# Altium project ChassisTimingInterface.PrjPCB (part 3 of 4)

## Sheet FPGA_ARTIX7.SchDoc: FPGA
size C; Organization: Altium Limited; Address1: L3, 12a Rodborough Rd; Address2: Frenchs Forest; Address3: NSW; Address4: Australia 2086; DocumentNumber: 7; SheetNumber: 7; SheetTotal: 12
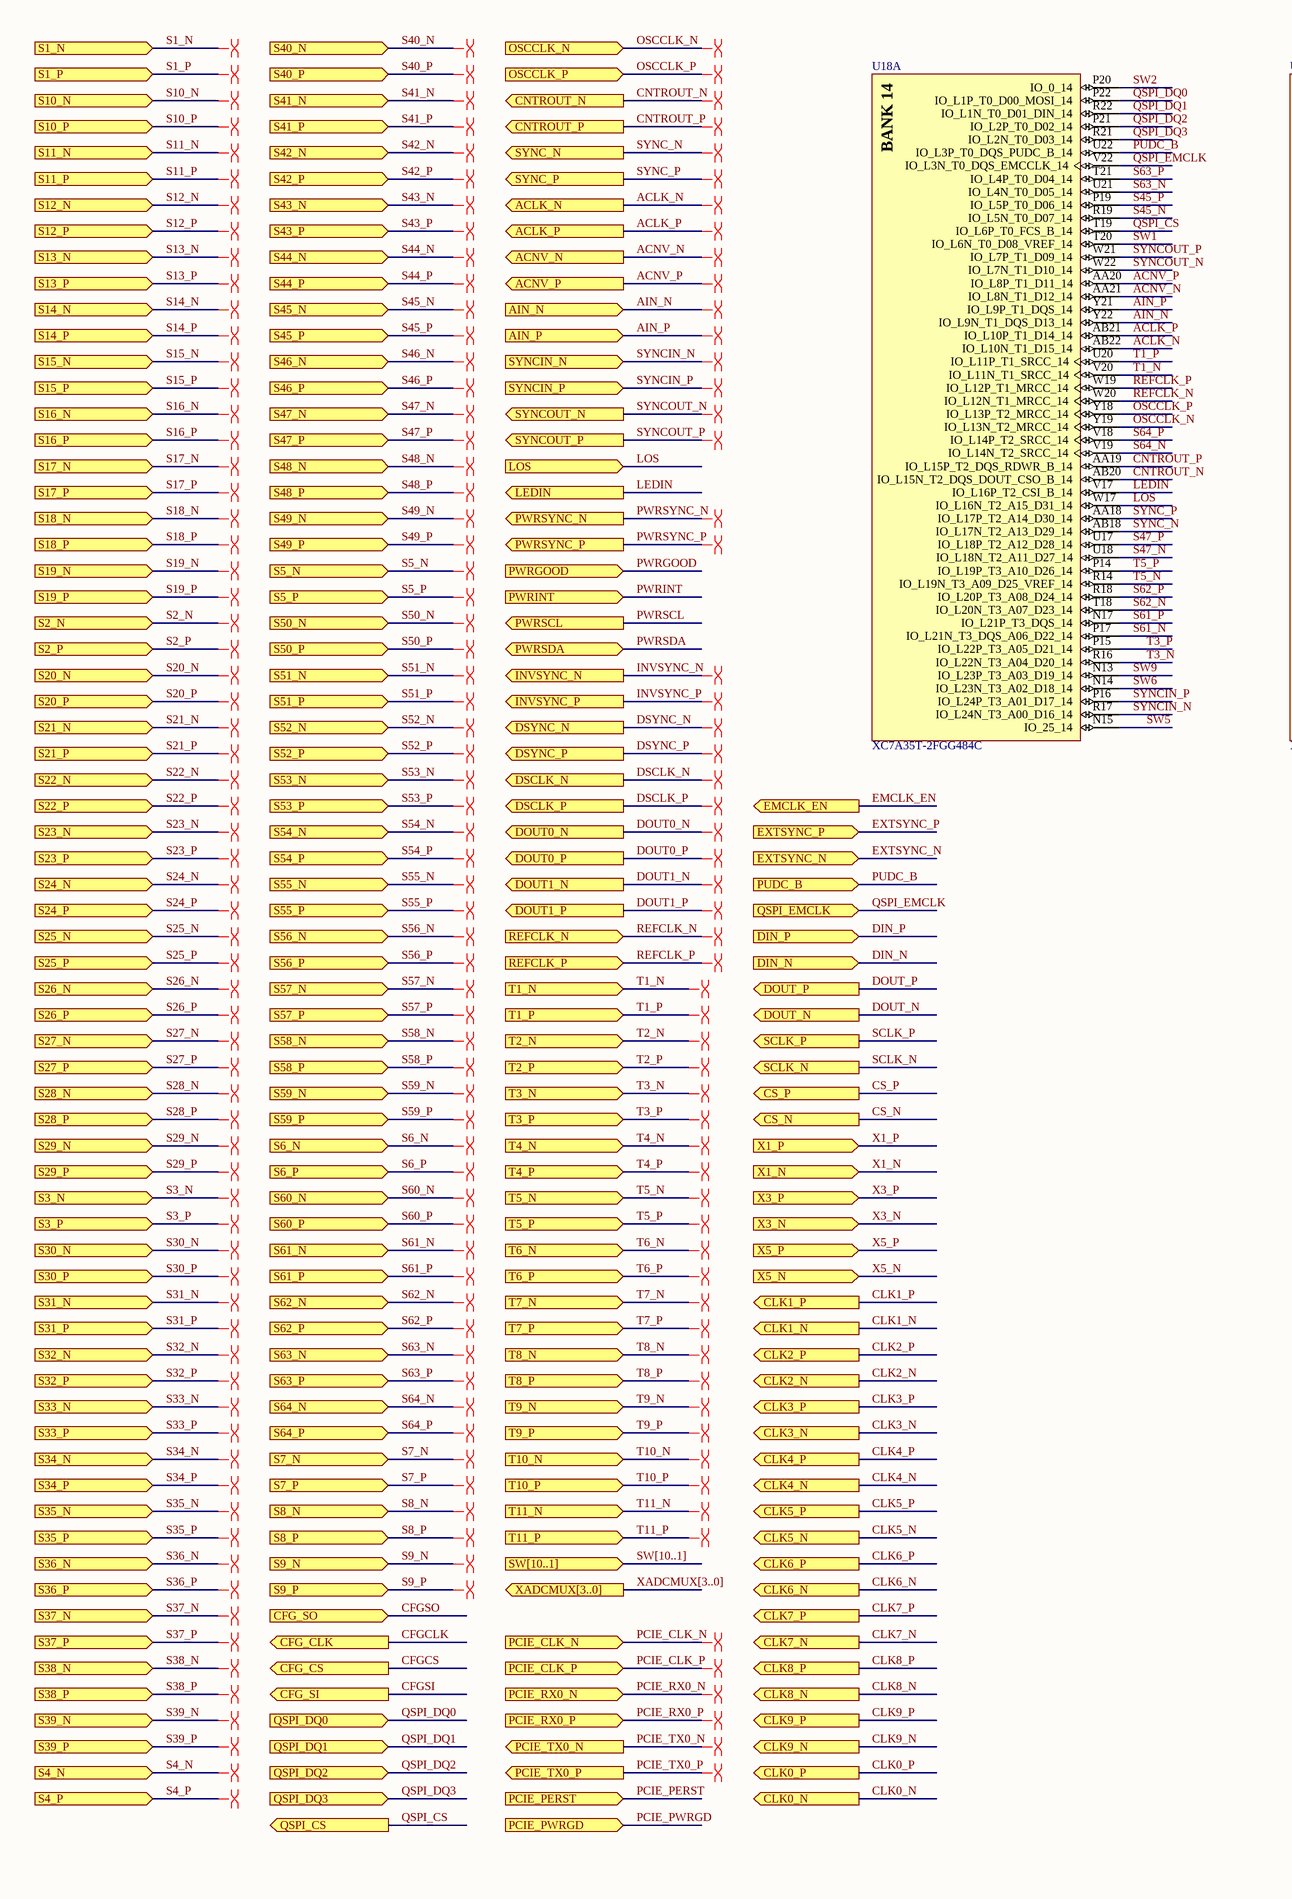
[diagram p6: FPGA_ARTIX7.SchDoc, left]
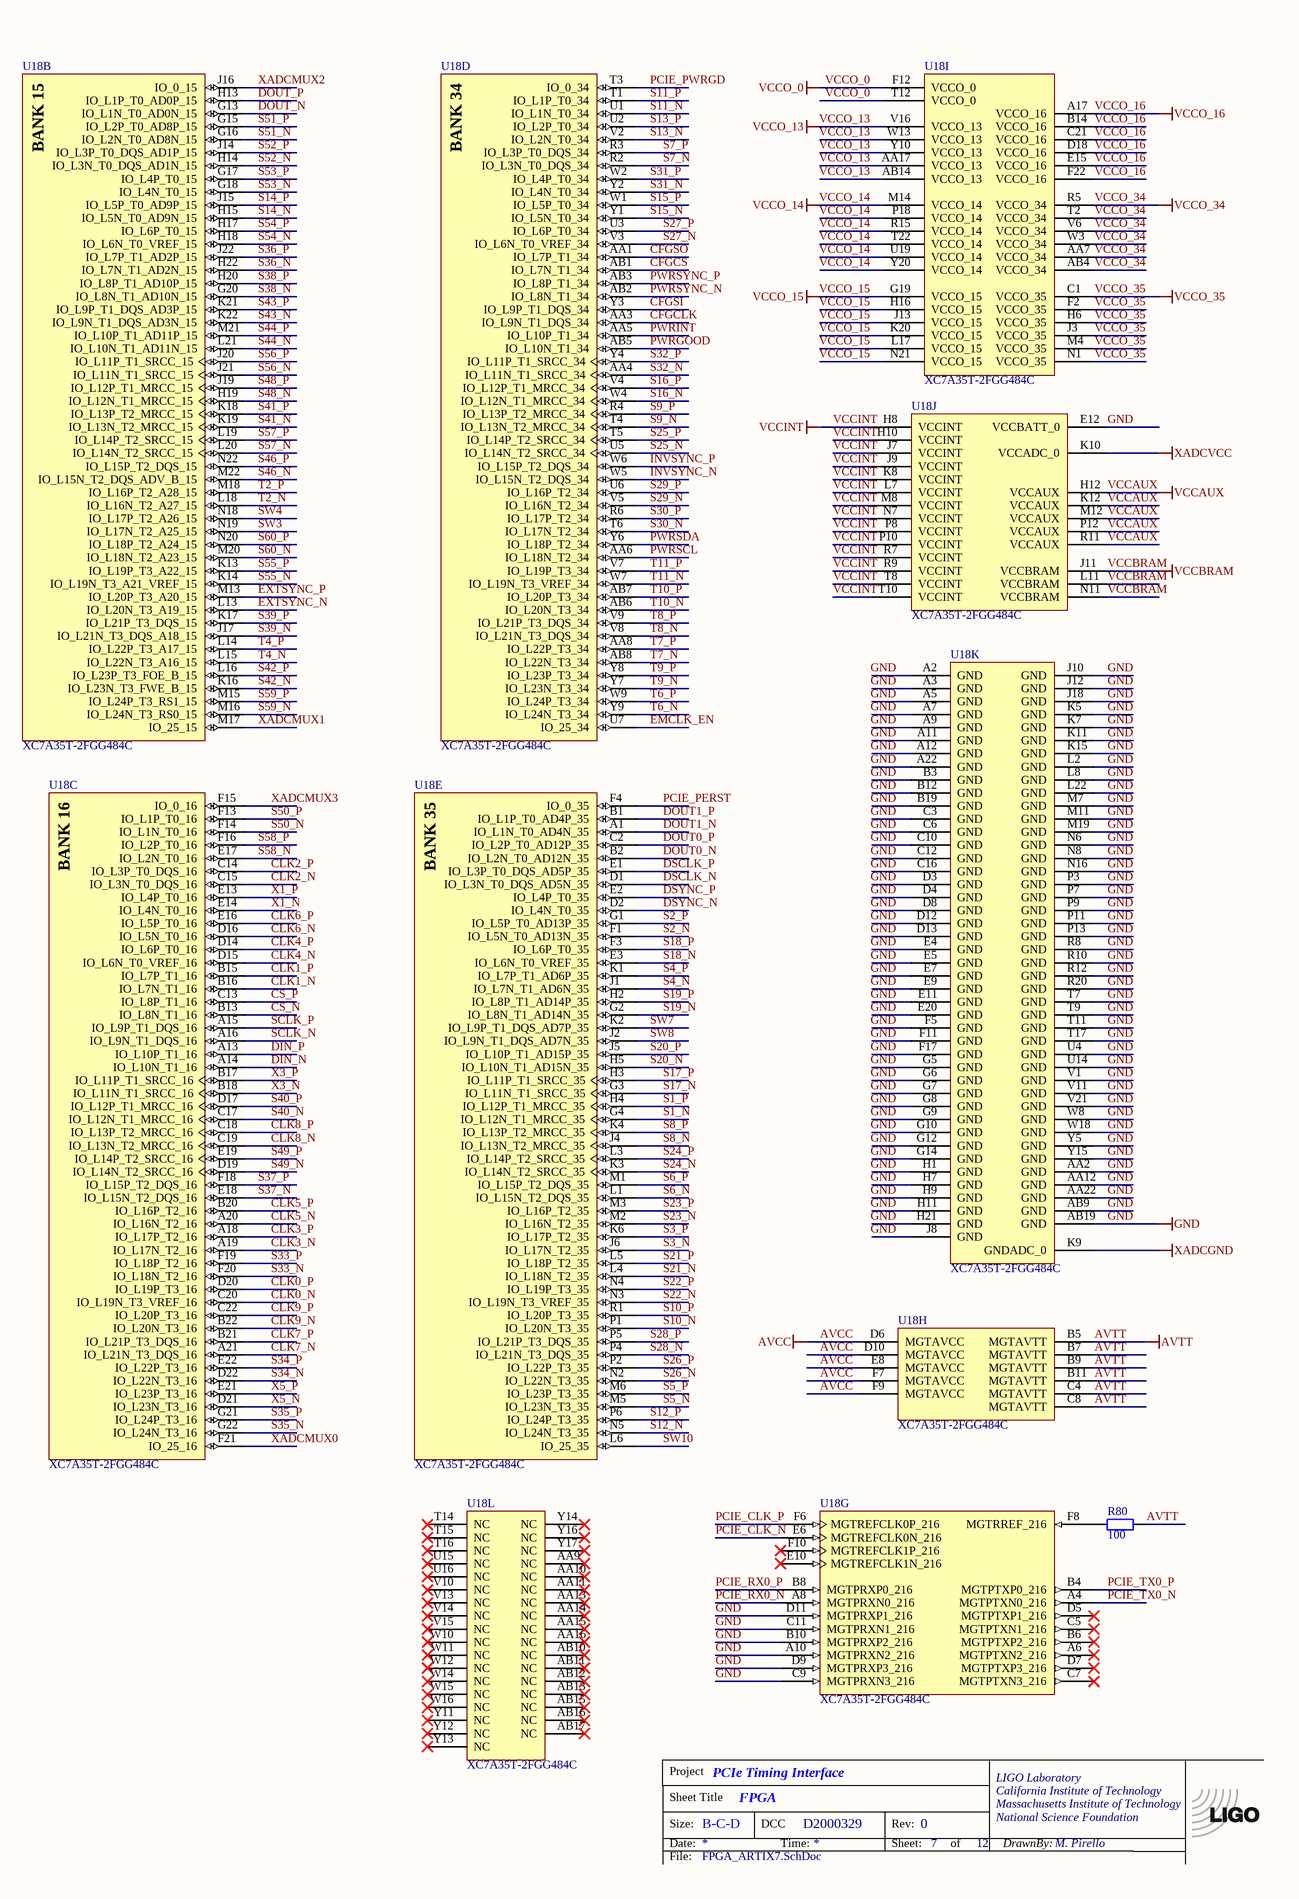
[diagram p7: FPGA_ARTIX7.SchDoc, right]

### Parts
(Parts that share a designator on the sheet are numbered #1, #2 ... from top to bottom, then left to right.)
*?#4  TitleBlock  (value not drawn)  (graphical)
R80  100  [CR1608-0603]
U18  XC7A35T-2FGG484C  [FGG484]  (parts A,B,C,D,E,G,H,I,J,K,L of 12)

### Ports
ACLK_N (out), ACLK_P (out), ACNV_N (out), ACNV_P (out), AIN_N (in), AIN_P (in), CFG_CLK (out), CFG_CS (out), CFG_SI (out), CFG_SO (in), CLK0_N (out), CLK0_P (out), CLK1_N (out), CLK1_P (out), CLK2_N (out), CLK2_P (out), CLK3_N (out), CLK3_P (out), CLK4_N (out), CLK4_P (out), CLK5_N (out), CLK5_P (out), CLK6_N (out), CLK6_P (out), CLK7_N (out), CLK7_P (out), CLK8_N (out), CLK8_P (out), CLK9_N (out), CLK9_P (out), CNTROUT_N (out), CNTROUT_P (out), CS_N (out), CS_P (out), DIN_N (in), DIN_P (in), DOUT0_N (out), DOUT0_P (out), DOUT1_N (out), DOUT1_P (out), DOUT_N (out), DOUT_P (out), DSCLK_N (out), DSCLK_P (out), DSYNC_N (out), DSYNC_P (out), EMCLK_EN (out), EXTSYNC_N (in), EXTSYNC_P (in), INVSYNC_N (out), INVSYNC_P (out), LEDIN (out), LOS (in), OSCCLK_N (in), OSCCLK_P (in), PCIE_CLK_N (in), PCIE_CLK_P (in), PCIE_PERST (in), PCIE_PWRGD (in), PCIE_RX0_N (in), PCIE_RX0_P (in), PCIE_TX0_N (out), PCIE_TX0_P (out), PUDC_B (in), PWRGOOD (in), PWRINT (in), PWRSCL (out), PWRSDA (bidir), PWRSYNC_N (out), PWRSYNC_P (out), QSPI_CS (out), QSPI_DQ0 (in), QSPI_DQ1 (in), QSPI_DQ2 (in), QSPI_DQ3 (in), QSPI_EMCLK (in), REFCLK_N (in), REFCLK_P (in), S1_N (in), S1_P (in), S2_N (in), S2_P (in), S3_N (in), S3_P (in), S4_N (in), S4_P (in), S5_N (in), S5_P (in), S6_N (in), S6_P (in), S7_N (in), S7_P (in), S8_N (in), S8_P (in), S9_N (in), S9_P (in), S10_N (in), S10_P (in), S11_N (in), S11_P (in), S12_N (in), S12_P (in), S13_N (in), S13_P (in), S14_N (in), S14_P (in), S15_N (in), S15_P (in), S16_N (in), S16_P (in), S17_N (in), S17_P (in), S18_N (in), S18_P (in), S19_N (in), S19_P (in), S20_N (in), S20_P (in), S21_N (in), S21_P (in), S22_N (in), S22_P (in), S23_N (in), S23_P (in), S24_N (in), S24_P (in), S25_N (in), S25_P (in), S26_N (in), S26_P (in), S27_N (in), S27_P (in), S28_N (in), S28_P (in), S29_N (in), S29_P (in), S30_N (in), S30_P (in), S31_N (in), S31_P (in), S32_N (in), S32_P (in), S33_N (in), S33_P (in), S34_N (in), S34_P (in), S35_N (in), S35_P (in), S36_N (in), S36_P (in), S37_N (in), S37_P (in), S38_N (in), S38_P (in), S39_N (in), S39_P (in), S40_N (in), S40_P (in), S41_N (in), S41_P (in), S42_N (in), S42_P (in), S43_N (in), S43_P (in), S44_N (in), S44_P (in), S45_N (in), S45_P (in), S46_N (in), S46_P (in), S47_N (in), S47_P (in), S48_N (in), S48_P (in), S49_N (in), S49_P (in), S50_N (in), S50_P (in), S51_N (in), S51_P (in), S52_N (in), S52_P (in), S53_N (in), S53_P (in), S54_N (in), S54_P (in), S55_N (in), S55_P (in), S56_N (in), S56_P (in), S57_N (in), S57_P (in), S58_N (in), S58_P (in), S59_N (in), S59_P (in), S60_N (in), S60_P (in), S61_N (in), S61_P (in), S62_N (in), S62_P (in), S63_N (in), S63_P (in), S64_N (in), S64_P (in), SCLK_N (out), SCLK_P (out), SW[10..1] (in), SYNC_N (out), SYNC_P (out), SYNCIN_N (in), SYNCIN_P (in), SYNCOUT_N (out), SYNCOUT_P (out), T1_N (in), T1_P (in), T2_N (in), T2_P (in), T3_N (in), T3_P (in), T4_N (in), T4_P (in), T5_N (in), T5_P (in), T6_N (in), T6_P (in), T7_N (in), T7_P (in), T8_N (in), T8_P (in), T9_N (in), T9_P (in), T10_N (in), T10_P (in), T11_N (in), T11_P (in), X1_N (in), X1_P (in), X3_N (in), X3_P (in), X5_N (in), X5_P (in), XADCMUX[3..0] (out)

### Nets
AVCC: U18.D6(MGTAVCC) U18.D10(MGTAVCC) U18.E8(MGTAVCC) U18.F7(MGTAVCC) U18.F9(MGTAVCC)
AVTT: R80.2 U18.B5(MGTAVTT) U18.B7(MGTAVTT) U18.B9(MGTAVTT) U18.B11(MGTAVTT) U18.C4(MGTAVTT) U18.C8(MGTAVTT)
GND: U18.A2(GND) U18.A3(GND) U18.A5(GND) U18.A7(GND) U18.A9(GND) U18.A10(MGTPRXN2_216) U18.A11(GND) U18.A12(GND) U18.A22(GND) U18.AA2(GND) U18.AA12(GND) U18.AA22(GND) U18.AB9(GND) U18.AB19(GND) U18.B3(GND) U18.B10(MGTPRXP2_216) U18.B12(GND) U18.B19(GND) U18.C3(GND) U18.C6(GND) U18.C9(MGTPRXN3_216) U18.C10(GND) U18.C11(MGTPRXN1_216) U18.C12(GND) U18.C16(GND) U18.D3(GND) U18.D4(GND) U18.D8(GND) U18.D9(MGTPRXP3_216) U18.D11(MGTPRXP1_216) U18.D12(GND) U18.D13(GND) U18.E4(GND) U18.E5(GND) U18.E7(GND) U18.E9(GND) U18.E11(GND) U18.E12(VCCBATT_0) U18.E20(GND) U18.F5(GND) U18.F11(GND) U18.F17(GND) U18.G5(GND) U18.G6(GND) U18.G7(GND) U18.G8(GND) U18.G9(GND) U18.G10(GND) U18.G12(GND) U18.G14(GND) U18.H1(GND) U18.H7(GND) U18.H9(GND) U18.H11(GND) U18.H21(GND) U18.J8(GND) U18.J10(GND) U18.J12(GND) U18.J18(GND) U18.K5(GND) U18.K7(GND) U18.K11(GND) U18.K15(GND) U18.L2(GND) U18.L8(GND) U18.L22(GND) U18.M7(GND) U18.M11(GND) U18.M19(GND) U18.N6(GND) U18.N8(GND) U18.N16(GND) U18.P3(GND) U18.P7(GND) U18.P9(GND) U18.P11(GND) U18.P13(GND) U18.R8(GND) U18.R10(GND) U18.R12(GND) U18.R20(GND) U18.T7(GND) U18.T9(GND) U18.T11(GND) U18.T17(GND) U18.U4(GND) U18.U14(GND) U18.V1(GND) U18.V11(GND) U18.V21(GND) U18.W8(GND) U18.W18(GND) U18.Y5(GND) U18.Y15(GND)
VCCAUX: U18.H12(VCCAUX) U18.K12(VCCAUX) U18.M12(VCCAUX) U18.P12(VCCAUX) U18.R11(VCCAUX)  [project net VCC1V8]
VCCINT: U18.H8(VCCINT) U18.H10(VCCINT) U18.J7(VCCINT) U18.J9(VCCINT) U18.J11(VCCBRAM) U18.K8(VCCINT) U18.L7(VCCINT) U18.L11(VCCBRAM) U18.M8(VCCINT) U18.N7(VCCINT) U18.N11(VCCBRAM) U18.P8(VCCINT) U18.P10(VCCINT) U18.R7(VCCINT) U18.R9(VCCINT) U18.T8(VCCINT) U18.T10(VCCINT)  [also labelled VCCBRAM]
VCCO_0: U18.A17(VCCO_16) U18.AA7(VCCO_34) U18.AA17(VCCO_13) U18.AB4(VCCO_34) U18.AB14(VCCO_13) U18.B14(VCCO_16) U18.C1(VCCO_35) U18.C21(VCCO_16) U18.D18(VCCO_16) U18.E15(VCCO_16) U18.F2(VCCO_35) U18.F12(VCCO_0) U18.F22(VCCO_16) U18.G19(VCCO_15) U18.H6(VCCO_35) U18.H16(VCCO_15) U18.J3(VCCO_35) U18.J13(VCCO_15) U18.K20(VCCO_15) U18.L17(VCCO_15) U18.M4(VCCO_35) U18.M14(VCCO_14) U18.N1(VCCO_35) U18.N21(VCCO_15) U18.P18(VCCO_14) U18.R5(VCCO_34) U18.R15(VCCO_14) U18.T2(VCCO_34) U18.T12(VCCO_0) U18.T22(VCCO_14) U18.U19(VCCO_14) U18.V6(VCCO_34) U18.V16(VCCO_13) U18.W3(VCCO_34) U18.W13(VCCO_13) U18.Y10(VCCO_13) U18.Y20(VCCO_14)  [also labelled VCCO_13, VCCO_14, VCCO_15, VCCO_16, VCCO_34, VCCO_35]  [project net VDD]
XADCGND: U18.K9(GNDADC_0)
XADCVCC: U18.K10(VCCADC_0)
ACLK_N: U18.AB22(IO_L10N_T1_D15_14) ; port ACLK_N  [project net CLOCK.ACLK_N]
ACLK_P: U18.AB21(IO_L10P_T1_D14_14) ; port ACLK_P  [project net CLOCK.ACLK_P]
ACNV_N: U18.AA21(IO_L8N_T1_D12_14) ; port ACNV_N  [project net CLOCK.ACNV_N]
ACNV_P: U18.AA20(IO_L8P_T1_D11_14) ; port ACNV_P  [project net CLOCK.ACNV_P]
AIN_N: U18.Y22(IO_L9N_T1_DQS_D13_14) ; port AIN_N  [project net CLOCK.AIN_N]
AIN_P: U18.Y21(IO_L9P_T1_DQS_14) ; port AIN_P  [project net CLOCK.AIN_P]
CFGCLK: U18.AA3(IO_L9N_T1_DQS_34) ; port CFG_CLK  [project net CFG_CLK]
CFGCS: U18.AB1(IO_L7N_T1_34) ; port CFG_CS  [project net CFG_CS]
CFGSI: U18.Y3(IO_L9P_T1_DQS_34) ; port CFG_SI  [project net CFG_SI]
CFGSO: U18.AA1(IO_L7P_T1_34) ; port CFG_SO  [project net CFG_SO]
CLK0_N: U18.C20(IO_L19N_T3_VREF_16) ; port CLK0_N  [project net BACKPLANE.CLK0_N]
CLK0_P: U18.D20(IO_L19P_T3_16) ; port CLK0_P  [project net BACKPLANE.CLK0_P]
CLK1_N: U18.B16(IO_L7N_T1_16) ; port CLK1_N  [project net BACKPLANE.CLK1_N]
CLK1_P: U18.B15(IO_L7P_T1_16) ; port CLK1_P  [project net BACKPLANE.CLK1_P]
CLK2_N: U18.C15(IO_L3N_T0_DQS_16) ; port CLK2_N  [project net BACKPLANE.CLK2_N]
CLK2_P: U18.C14(IO_L3P_T0_DQS_16) ; port CLK2_P  [project net BACKPLANE.CLK2_P]
CLK3_N: U18.A19(IO_L17N_T2_16) ; port CLK3_N  [project net BACKPLANE.CLK3_N]
CLK3_P: U18.A18(IO_L17P_T2_16) ; port CLK3_P  [project net BACKPLANE.CLK3_P]
CLK4_N: U18.D15(IO_L6N_T0_VREF_16) ; port CLK4_N  [project net BACKPLANE.CLK4_N]
CLK4_P: U18.D14(IO_L6P_T0_16) ; port CLK4_P  [project net BACKPLANE.CLK4_P]
CLK5_N: U18.A20(IO_L16N_T2_16) ; port CLK5_N  [project net BACKPLANE.CLK5_N]
CLK5_P: U18.B20(IO_L16P_T2_16) ; port CLK5_P  [project net BACKPLANE.CLK5_P]
CLK6_N: U18.D16(IO_L5N_T0_16) ; port CLK6_N  [project net BACKPLANE.CLK6_N]
CLK6_P: U18.E16(IO_L5P_T0_16) ; port CLK6_P  [project net BACKPLANE.CLK6_P]
CLK7_N: U18.A21(IO_L21N_T3_DQS_16) ; port CLK7_N  [project net BACKPLANE.CLK7_N]
CLK7_P: U18.B21(IO_L21P_T3_DQS_16) ; port CLK7_P  [project net BACKPLANE.CLK7_P]
CLK8_N: U18.C19(IO_L13N_T2_MRCC_16) ; port CLK8_N  [project net BACKPLANE.CLK8_N]
CLK8_P: U18.C18(IO_L13P_T2_MRCC_16) ; port CLK8_P  [project net BACKPLANE.CLK8_P]
CLK9_N: U18.B22(IO_L20N_T3_16) ; port CLK9_N  [project net BACKPLANE.CLK9_N]
CLK9_P: U18.C22(IO_L20P_T3_16) ; port CLK9_P  [project net BACKPLANE.CLK9_P]
CNTROUT_N: U18.AB20(IO_L15N_T2_DQS_DOUT_CSO_B_14) ; port CNTROUT_N  [project net CLOCK.CNTROUT_N]
CNTROUT_P: U18.AA19(IO_L15P_T2_DQS_RDWR_B_14) ; port CNTROUT_P  [project net CLOCK.CNTROUT_P]
CS_N: U18.B13(IO_L8N_T1_16) ; port CS_N  [project net BACKPLANE.CS_N]
CS_P: U18.C13(IO_L8P_T1_16) ; port CS_P  [project net BACKPLANE.CS_P]
DIN_N: U18.A14(IO_L10N_T1_16) ; port DIN_N  [project net BACKPLANE.DIN_N]
DIN_P: U18.A13(IO_L10P_T1_16) ; port DIN_P  [project net BACKPLANE.DIN_P]
DOUT0_N: U18.B2(IO_L2N_T0_AD12N_35) ; port DOUT0_N  [project net DAC_REF.DOUT0_N]
DOUT0_P: U18.C2(IO_L2P_T0_AD12P_35) ; port DOUT0_P  [project net DAC_REF.DOUT0_P]
DOUT1_N: U18.A1(IO_L1N_T0_AD4N_35) ; port DOUT1_N  [project net DAC_REF.DOUT1_N]
DOUT1_P: U18.B1(IO_L1P_T0_AD4P_35) ; port DOUT1_P  [project net DAC_REF.DOUT1_P]
DOUT_N: U18.G13(IO_L1N_T0_AD0N_15) ; port DOUT_N  [project net BACKPLANE.DOUT_N]
DOUT_P: U18.H13(IO_L1P_T0_AD0P_15) ; port DOUT_P  [project net BACKPLANE.DOUT_P]
DSCLK_N: U18.D1(IO_L3N_T0_DQS_AD5N_35) ; port DSCLK_N  [project net DAC_REF.DSCLK_N]
DSCLK_P: U18.E1(IO_L3P_T0_DQS_AD5P_35) ; port DSCLK_P  [project net DAC_REF.DSCLK_P]
DSYNC_N: U18.D2(IO_L4N_T0_35) ; port DSYNC_N  [project net DAC_REF.DSYNC_N]
DSYNC_P: U18.E2(IO_L4P_T0_35) ; port DSYNC_P  [project net DAC_REF.DSYNC_P]
EMCLK_EN: U18.U7(IO_25_34) ; port EMCLK_EN  [project net SQSPI.EMCLK_EN]
EXTSYNC_N: U18.L13(IO_L20N_T3_A19_15) ; port EXTSYNC_N  [project net EXT_SYNC.EXTSYNC_N]
EXTSYNC_P: U18.M13(IO_L20P_T3_A20_15) ; port EXTSYNC_P  [project net EXT_SYNC.EXTSYNC_P]
INVSYNC_N: U18.W5(IO_L15N_T2_DQS_34) ; port INVSYNC_N  [project net DAC_REF.INVSYNC_N]
INVSYNC_P: U18.W6(IO_L15P_T2_DQS_34) ; port INVSYNC_P  [project net DAC_REF.INVSYNC_P]
LEDIN: U18.V17(IO_L16P_T2_CSI_B_14) ; port LEDIN  [project net SFPIN.LEDIN]
LOS: U18.W17(IO_L16N_T2_A15_D31_14) ; port LOS  [project net SFPIN.LOS]
OSCCLK_N: U18.Y19(IO_L13N_T2_MRCC_14) ; port OSCCLK_N  [project net CLOCK.OSCCLK_N]
OSCCLK_P: U18.Y18(IO_L13P_T2_MRCC_14) ; port OSCCLK_P  [project net CLOCK.OSCCLK_P]
PCIE_CLK_N: U18.E6(MGTREFCLK0N_216) ; port PCIE_CLK_N  [project net PCIE.PCIE_CLK_N]
PCIE_CLK_P: U18.F6(MGTREFCLK0P_216) ; port PCIE_CLK_P  [project net PCIE.PCIE_CLK_P]
PCIE_PERST: U18.F4(IO_0_35) ; port PCIE_PERST  [project net PCIE.PCIE_PERST]
PCIE_PWRGD: U18.T3(IO_0_34) ; port PCIE_PWRGD  [project net PCIE.PCIE_PWRGD]
PCIE_RX0_N: U18.A8(MGTPRXN0_216) ; port PCIE_RX0_N  [project net PCIE.PCIE_RX0_N]
PCIE_RX0_P: U18.B8(MGTPRXP0_216) ; port PCIE_RX0_P  [project net PCIE.PCIE_RX0_P]
PCIE_TX0_N: U18.A4(MGTPTXN0_216) ; port PCIE_TX0_N  [project net PCIE.PCIE_TX0_N]
PCIE_TX0_P: U18.B4(MGTPTXP0_216) ; port PCIE_TX0_P  [project net PCIE.PCIE_TX0_P]
PUDC_B: U18.U22(IO_L3P_T0_DQS_PUDC_B_14) ; port PUDC_B  [project net SQSPI.PUDC_B]
PWRGOOD: U18.AB5(IO_L10N_T1_34) ; port PWRGOOD  [project net POWER.PWRGOOD]
PWRINT: U18.AA5(IO_L10P_T1_34) ; port PWRINT  [project net POWER.PWRINT]
PWRSCL: U18.AA6(IO_L18N_T2_34) ; port PWRSCL  [project net POWER.PWRSCL]
PWRSDA: U18.Y6(IO_L18P_T2_34) ; port PWRSDA  [project net POWER.PWRSDA]
PWRSYNC_N: U18.AB2(IO_L8N_T1_34) ; port PWRSYNC_N  [project net POWER.PWRSYNC_N]
PWRSYNC_P: U18.AB3(IO_L8P_T1_34) ; port PWRSYNC_P  [project net POWER.PWRSYNC_P]
QSPI_CS: U18.T19(IO_L6P_T0_FCS_B_14) ; port QSPI_CS  [project net SQSPI.QSPI_CS]
QSPI_DQ0: U18.P22(IO_L1P_T0_D00_MOSI_14) ; port QSPI_DQ0  [project net SQSPI.QSPI_DQ0]
QSPI_DQ1: U18.R22(IO_L1N_T0_D01_DIN_14) ; port QSPI_DQ1  [project net SQSPI.QSPI_DQ1]
QSPI_DQ2: U18.P21(IO_L2P_T0_D02_14) ; port QSPI_DQ2  [project net SQSPI.QSPI_DQ2]
QSPI_DQ3: U18.R21(IO_L2N_T0_D03_14) ; port QSPI_DQ3  [project net SQSPI.QSPI_DQ3]
QSPI_EMCLK: U18.V22(IO_L3N_T0_DQS_EMCCLK_14) ; port QSPI_EMCLK  [project net SQSPI.QSPI_EMCLK]
REFCLK_N: U18.W20(IO_L12N_T1_MRCC_14) ; port REFCLK_N  [project net DAC_REF.REFCLK_N]
REFCLK_P: U18.W19(IO_L12P_T1_MRCC_14) ; port REFCLK_P  [project net DAC_REF.REFCLK_P]
S1_N: U18.G4(IO_L12N_T1_MRCC_35) ; port S1_N  [project net S1_16.S1_N]
S1_P: U18.H4(IO_L12P_T1_MRCC_35) ; port S1_P  [project net S1_16.S1_P]
S2_N: U18.F1(IO_L5N_T0_AD13N_35) ; port S2_N  [project net S1_16.S2_N]
S2_P: U18.G1(IO_L5P_T0_AD13P_35) ; port S2_P  [project net S1_16.S2_P]
S3_N: U18.J6(IO_L17N_T2_35) ; port S3_N  [project net S1_16.S3_N]
S3_P: U18.K6(IO_L17P_T2_35) ; port S3_P  [project net S1_16.S3_P]
S4_N: U18.J1(IO_L7N_T1_AD6N_35) ; port S4_N  [project net S1_16.S4_N]
S4_P: U18.K1(IO_L7P_T1_AD6P_35) ; port S4_P  [project net S1_16.S4_P]
S5_N: U18.M5(IO_L23N_T3_35) ; port S5_N  [project net S1_16.S5_N]
S5_P: U18.M6(IO_L23P_T3_35) ; port S5_P  [project net S1_16.S5_P]
S6_N: U18.L1(IO_L15N_T2_DQS_35) ; port S6_N  [project net S1_16.S6_N]
S6_P: U18.M1(IO_L15P_T2_DQS_35) ; port S6_P  [project net S1_16.S6_P]
S7_N: U18.R2(IO_L3N_T0_DQS_34) ; port S7_N  [project net S1_16.S7_N]
S7_P: U18.R3(IO_L3P_T0_DQS_34) ; port S7_P  [project net S1_16.S7_P]
S8_N: U18.J4(IO_L13N_T2_MRCC_35) ; port S8_N  [project net S1_16.S8_N]
S8_P: U18.K4(IO_L13P_T2_MRCC_35) ; port S8_P  [project net S1_16.S8_P]
S9_N: U18.T4(IO_L13N_T2_MRCC_34) ; port S9_N  [project net S1_16.S9_N]
S9_P: U18.R4(IO_L13P_T2_MRCC_34) ; port S9_P  [project net S1_16.S9_P]
S10_N: U18.P1(IO_L20N_T3_35) ; port S10_N
S10_P: U18.R1(IO_L20P_T3_35) ; port S10_P
S11_N: U18.U1(IO_L1N_T0_34) ; port S11_N
S11_P: U18.T1(IO_L1P_T0_34) ; port S11_P
S12_N: U18.N5(IO_L24N_T3_35) ; port S12_N
S12_P: U18.P6(IO_L24P_T3_35) ; port S12_P
S13_N: U18.V2(IO_L2N_T0_34) ; port S13_N
S13_P: U18.U2(IO_L2P_T0_34) ; port S13_P
S14_N: U18.H15(IO_L5N_T0_AD9N_15) ; port S14_N
S14_P: U18.J15(IO_L5P_T0_AD9P_15) ; port S14_P
S15_N: U18.Y1(IO_L5N_T0_34) ; port S15_N
S15_P: U18.W1(IO_L5P_T0_34) ; port S15_P
S16_N: U18.W4(IO_L12N_T1_MRCC_34) ; port S16_N
S16_P: U18.V4(IO_L12P_T1_MRCC_34) ; port S16_P
S17_N: U18.G3(IO_L11N_T1_SRCC_35) ; port S17_N  [project net S17_32.S17_N]
S17_P: U18.H3(IO_L11P_T1_SRCC_35) ; port S17_P  [project net S17_32.S17_P]
S18_N: U18.E3(IO_L6N_T0_VREF_35) ; port S18_N  [project net S17_32.S18_N]
S18_P: U18.F3(IO_L6P_T0_35) ; port S18_P  [project net S17_32.S18_P]
S19_N: U18.G2(IO_L8N_T1_AD14N_35) ; port S19_N  [project net S17_32.S19_N]
S19_P: U18.H2(IO_L8P_T1_AD14P_35) ; port S19_P  [project net S17_32.S19_P]
S20_N: U18.H5(IO_L10N_T1_AD15N_35) ; port S20_N  [project net S17_32.S20_N]
S20_P: U18.J5(IO_L10P_T1_AD15P_35) ; port S20_P  [project net S17_32.S20_P]
S21_N: U18.L4(IO_L18N_T2_35) ; port S21_N  [project net S17_32.S21_N]
S21_P: U18.L5(IO_L18P_T2_35) ; port S21_P  [project net S17_32.S21_P]
S22_N: U18.N3(IO_L19N_T3_VREF_35) ; port S22_N  [project net S17_32.S22_N]
S22_P: U18.N4(IO_L19P_T3_35) ; port S22_P  [project net S17_32.S22_P]
S23_N: U18.M2(IO_L16N_T2_35) ; port S23_N  [project net S17_32.S23_N]
S23_P: U18.M3(IO_L16P_T2_35) ; port S23_P  [project net S17_32.S23_P]
S24_N: U18.K3(IO_L14N_T2_SRCC_35) ; port S24_N  [project net S17_32.S24_N]
S24_P: U18.L3(IO_L14P_T2_SRCC_35) ; port S24_P  [project net S17_32.S24_P]
S25_N: U18.U5(IO_L14N_T2_SRCC_34) ; port S25_N  [project net S17_32.S25_N]
S25_P: U18.T5(IO_L14P_T2_SRCC_34) ; port S25_P  [project net S17_32.S25_P]
S26_N: U18.N2(IO_L22N_T3_35) ; port S26_N  [project net S17_32.S26_N]
S26_P: U18.P2(IO_L22P_T3_35) ; port S26_P  [project net S17_32.S26_P]
S27_N: U18.V3(IO_L6N_T0_VREF_34) ; port S27_N  [project net S17_32.S27_N]
S27_P: U18.U3(IO_L6P_T0_34) ; port S27_P  [project net S17_32.S27_P]
S28_N: U18.P4(IO_L21N_T3_DQS_35) ; port S28_N  [project net S17_32.S28_N]
S28_P: U18.P5(IO_L21P_T3_DQS_35) ; port S28_P  [project net S17_32.S28_P]
S29_N: U18.V5(IO_L16N_T2_34) ; port S29_N  [project net S17_32.S29_N]
S29_P: U18.U6(IO_L16P_T2_34) ; port S29_P  [project net S17_32.S29_P]
S30_N: U18.T6(IO_L17N_T2_34) ; port S30_N  [project net S17_32.S30_N]
S30_P: U18.R6(IO_L17P_T2_34) ; port S30_P  [project net S17_32.S30_P]
S31_N: U18.Y2(IO_L4N_T0_34) ; port S31_N  [project net S17_32.S31_N]
S31_P: U18.W2(IO_L4P_T0_34) ; port S31_P  [project net S17_32.S31_P]
S32_N: U18.AA4(IO_L11N_T1_SRCC_34) ; port S32_N  [project net S17_32.S32_N]
S32_P: U18.Y4(IO_L11P_T1_SRCC_34) ; port S32_P  [project net S17_32.S32_P]
S33_N: U18.F20(IO_L18N_T2_16) ; port S33_N  [project net S33_48.S33_N]
S33_P: U18.F19(IO_L18P_T2_16) ; port S33_P  [project net S33_48.S33_P]
S34_N: U18.D22(IO_L22N_T3_16) ; port S34_N  [project net S33_48.S34_N]
S34_P: U18.E22(IO_L22P_T3_16) ; port S34_P  [project net S33_48.S34_P]
S35_N: U18.G22(IO_L24N_T3_16) ; port S35_N  [project net S33_48.S35_N]
S35_P: U18.G21(IO_L24P_T3_16) ; port S35_P  [project net S33_48.S35_P]
S36_N: U18.H22(IO_L7N_T1_AD2N_15) ; port S36_N  [project net S33_48.S36_N]
S36_P: U18.J22(IO_L7P_T1_AD2P_15) ; port S36_P  [project net S33_48.S36_P]
S37_N: U18.E18(IO_L15N_T2_DQS_16) ; port S37_N  [project net S33_48.S37_N]
S37_P: U18.F18(IO_L15P_T2_DQS_16) ; port S37_P  [project net S33_48.S37_P]
S38_N: U18.G20(IO_L8N_T1_AD10N_15) ; port S38_N  [project net S33_48.S38_N]
S38_P: U18.H20(IO_L8P_T1_AD10P_15) ; port S38_P  [project net S33_48.S38_P]
S39_N: U18.J17(IO_L21N_T3_DQS_A18_15) ; port S39_N  [project net S33_48.S39_N]
S39_P: U18.K17(IO_L21P_T3_DQS_15) ; port S39_P  [project net S33_48.S39_P]
S40_N: U18.C17(IO_L12N_T1_MRCC_16) ; port S40_N  [project net S33_48.S40_N]
S40_P: U18.D17(IO_L12P_T1_MRCC_16) ; port S40_P  [project net S33_48.S40_P]
S41_N: U18.K19(IO_L13N_T2_MRCC_15) ; port S41_N  [project net S33_48.S41_N]
S41_P: U18.K18(IO_L13P_T2_MRCC_15) ; port S41_P  [project net S33_48.S41_P]
S42_N: U18.K16(IO_L23N_T3_FWE_B_15) ; port S42_N  [project net S33_48.S42_N]
S42_P: U18.L16(IO_L23P_T3_FOE_B_15) ; port S42_P  [project net S33_48.S42_P]
S43_N: U18.K22(IO_L9N_T1_DQS_AD3N_15) ; port S43_N  [project net S33_48.S43_N]
S43_P: U18.K21(IO_L9P_T1_DQS_AD3P_15) ; port S43_P  [project net S33_48.S43_P]
S44_N: U18.L21(IO_L10N_T1_AD11N_15) ; port S44_N  [project net S33_48.S44_N]
S44_P: U18.M21(IO_L10P_T1_AD11P_15) ; port S44_P  [project net S33_48.S44_P]
S45_N: U18.R19(IO_L5N_T0_D07_14) ; port S45_N  [project net S33_48.S45_N]
S45_P: U18.P19(IO_L5P_T0_D06_14) ; port S45_P  [project net S33_48.S45_P]
S46_N: U18.M22(IO_L15N_T2_DQS_ADV_B_15) ; port S46_N  [project net S33_48.S46_N]
S46_P: U18.N22(IO_L15P_T2_DQS_15) ; port S46_P  [project net S33_48.S46_P]
S47_N: U18.U18(IO_L18N_T2_A11_D27_14) ; port S47_N  [project net S33_48.S47_N]
S47_P: U18.U17(IO_L18P_T2_A12_D28_14) ; port S47_P  [project net S33_48.S47_P]
S48_N: U18.H19(IO_L12N_T1_MRCC_15) ; port S48_N  [project net S33_48.S48_N]
S48_P: U18.J19(IO_L12P_T1_MRCC_15) ; port S48_P  [project net S33_48.S48_P]
S49_N: U18.D19(IO_L14N_T2_SRCC_16) ; port S49_N  [project net S49_64.S49_N]
S49_P: U18.E19(IO_L14P_T2_SRCC_16) ; port S49_P  [project net S49_64.S49_P]
S50_N: U18.F14(IO_L1N_T0_16) ; port S50_N  [project net S49_64.S50_N]
S50_P: U18.F13(IO_L1P_T0_16) ; port S50_P  [project net S49_64.S50_P]
S51_N: U18.G16(IO_L2N_T0_AD8N_15) ; port S51_N  [project net S49_64.S51_N]
S51_P: U18.G15(IO_L2P_T0_AD8P_15) ; port S51_P  [project net S49_64.S51_P]
S52_N: U18.H14(IO_L3N_T0_DQS_AD1N_15) ; port S52_N  [project net S49_64.S52_N]
S52_P: U18.J14(IO_L3P_T0_DQS_AD1P_15) ; port S52_P  [project net S49_64.S52_P]
S53_N: U18.G18(IO_L4N_T0_15) ; port S53_N  [project net S49_64.S53_N]
S53_P: U18.G17(IO_L4P_T0_15) ; port S53_P  [project net S49_64.S53_P]
S54_N: U18.H18(IO_L6N_T0_VREF_15) ; port S54_N  [project net S49_64.S54_N]
S54_P: U18.H17(IO_L6P_T0_15) ; port S54_P  [project net S49_64.S54_P]
S55_N: U18.K14(IO_L19N_T3_A21_VREF_15) ; port S55_N  [project net S49_64.S55_N]
S55_P: U18.K13(IO_L19P_T3_A22_15) ; port S55_P  [project net S49_64.S55_P]
S56_N: U18.J21(IO_L11N_T1_SRCC_15) ; port S56_N  [project net S49_64.S56_N]
S56_P: U18.J20(IO_L11P_T1_SRCC_15) ; port S56_P  [project net S49_64.S56_P]
S57_N: U18.L20(IO_L14N_T2_SRCC_15) ; port S57_N  [project net S49_64.S57_N]
S57_P: U18.L19(IO_L14P_T2_SRCC_15) ; port S57_P  [project net S49_64.S57_P]
S58_N: U18.E17(IO_L2N_T0_16) ; port S58_N  [project net S49_64.S58_N]
S58_P: U18.F16(IO_L2P_T0_16) ; port S58_P  [project net S49_64.S58_P]
S59_N: U18.M16(IO_L24N_T3_RS0_15) ; port S59_N  [project net S49_64.S59_N]
S59_P: U18.M15(IO_L24P_T3_RS1_15) ; port S59_P  [project net S49_64.S59_P]
S60_N: U18.M20(IO_L18N_T2_A23_15) ; port S60_N  [project net S49_64.S60_N]
S60_P: U18.N20(IO_L18P_T2_A24_15) ; port S60_P  [project net S49_64.S60_P]
S61_N: U18.P17(IO_L21N_T3_DQS_A06_D22_14) ; port S61_N  [project net S49_64.S61_N]
S61_P: U18.N17(IO_L21P_T3_DQS_14) ; port S61_P  [project net S49_64.S61_P]
S62_N: U18.T18(IO_L20N_T3_A07_D23_14) ; port S62_N  [project net S49_64.S62_N]
S62_P: U18.R18(IO_L20P_T3_A08_D24_14) ; port S62_P  [project net S49_64.S62_P]
S63_N: U18.U21(IO_L4N_T0_D05_14) ; port S63_N  [project net S49_64.S63_N]
S63_P: U18.T21(IO_L4P_T0_D04_14) ; port S63_P  [project net S49_64.S63_P]
S64_N: U18.V19(IO_L14N_T2_SRCC_14) ; port S64_N  [project net S49_64.S64_N]
S64_P: U18.V18(IO_L14P_T2_SRCC_14) ; port S64_P  [project net S49_64.S64_P]
SCLK_N: U18.A16(IO_L9N_T1_DQS_16) ; port SCLK_N  [project net BACKPLANE.SCLK_N]
SCLK_P: U18.A15(IO_L9P_T1_DQS_16) ; port SCLK_P  [project net BACKPLANE.SCLK_P]
SW1: U18.T20(IO_L6N_T0_D08_VREF_14)
SW2: U18.P20(IO_0_14)
SW3: U18.N19(IO_L17N_T2_A25_15)
SW4: U18.N18(IO_L17P_T2_A26_15)
SW5: U18.N15(IO_25_14)
SW6: U18.N14(IO_L23N_T3_A02_D18_14)
SW7: U18.K2(IO_L9P_T1_DQS_AD7P_35)
SW8: U18.J2(IO_L9N_T1_DQS_AD7N_35)
SW9: U18.N13(IO_L23P_T3_A03_D19_14)
SW10: U18.L6(IO_25_35)
SYNC_N: U18.AB18(IO_L17N_T2_A13_D29_14) ; port SYNC_N  [project net CLOCK.SYNC_N]
SYNC_P: U18.AA18(IO_L17P_T2_A14_D30_14) ; port SYNC_P  [project net CLOCK.SYNC_P]
SYNCIN_N: U18.R17(IO_L24N_T3_A00_D16_14) ; port SYNCIN_N  [project net SFPIN.SYNCIN_N]
SYNCIN_P: U18.P16(IO_L24P_T3_A01_D17_14) ; port SYNCIN_P  [project net SFPIN.SYNCIN_P]
SYNCOUT_N: U18.W22(IO_L7N_T1_D10_14) ; port SYNCOUT_N  [project net SFPIN.SYNCOUT_N]
SYNCOUT_P: U18.W21(IO_L7P_T1_D09_14) ; port SYNCOUT_P  [project net SFPIN.SYNCOUT_P]
T1_N: U18.V20(IO_L11N_T1_SRCC_14) ; port T1_N  [project net T1_11.T1_N]
T1_P: U18.U20(IO_L11P_T1_SRCC_14) ; port T1_P  [project net T1_11.T1_P]
T2_N: U18.L18(IO_L16N_T2_A27_15) ; port T2_N  [project net T1_11.T2_N]
T2_P: U18.M18(IO_L16P_T2_A28_15) ; port T2_P  [project net T1_11.T2_P]
T3_N: U18.R16(IO_L22N_T3_A04_D20_14) ; port T3_N  [project net T1_11.T3_N]
T3_P: U18.P15(IO_L22P_T3_A05_D21_14) ; port T3_P  [project net T1_11.T3_P]
T4_N: U18.L15(IO_L22N_T3_A16_15) ; port T4_N  [project net T1_11.T4_N]
T4_P: U18.L14(IO_L22P_T3_A17_15) ; port T4_P  [project net T1_11.T4_P]
T5_N: U18.R14(IO_L19N_T3_A09_D25_VREF_14) ; port T5_N  [project net T1_11.T5_N]
T5_P: U18.P14(IO_L19P_T3_A10_D26_14) ; port T5_P  [project net T1_11.T5_P]
T6_N: U18.Y9(IO_L24N_T3_34) ; port T6_N  [project net T1_11.T6_N]
T6_P: U18.W9(IO_L24P_T3_34) ; port T6_P  [project net T1_11.T6_P]
T7_N: U18.AB8(IO_L22N_T3_34) ; port T7_N  [project net T1_11.T7_N]
T7_P: U18.AA8(IO_L22P_T3_34) ; port T7_P  [project net T1_11.T7_P]
T8_N: U18.V8(IO_L21N_T3_DQS_34) ; port T8_N  [project net T1_11.T8_N]
T8_P: U18.V9(IO_L21P_T3_DQS_34) ; port T8_P  [project net T1_11.T8_P]
T9_N: U18.Y7(IO_L23N_T3_34) ; port T9_N  [project net T1_11.T9_N]
T9_P: U18.Y8(IO_L23P_T3_34) ; port T9_P  [project net T1_11.T9_P]
T10_N: U18.AB6(IO_L20N_T3_34) ; port T10_N
T10_P: U18.AB7(IO_L20P_T3_34) ; port T10_P
T11_N: U18.W7(IO_L19N_T3_VREF_34) ; port T11_N
T11_P: U18.V7(IO_L19P_T3_34) ; port T11_P
X1_N: U18.E14(IO_L4N_T0_16) ; port X1_N  [project net BACKPLANE.X1_N]
X1_P: U18.E13(IO_L4P_T0_16) ; port X1_P  [project net BACKPLANE.X1_P]
X3_N: U18.B18(IO_L11N_T1_SRCC_16) ; port X3_N  [project net BACKPLANE.X3_N]
X3_P: U18.B17(IO_L11P_T1_SRCC_16) ; port X3_P  [project net BACKPLANE.X3_P]
X5_N: U18.D21(IO_L23N_T3_16) ; port X5_N  [project net BACKPLANE.X5_N]
X5_P: U18.E21(IO_L23P_T3_16) ; port X5_P  [project net BACKPLANE.X5_P]
XADCMUX0: U18.F21(IO_25_16)  [project net XMUX0]
XADCMUX1: U18.M17(IO_25_15)  [project net XMUX1]
XADCMUX2: U18.J16(IO_0_15)  [project net XMUX2]
XADCMUX3: U18.F15(IO_0_16)  [project net XMUX3]
NetR80_1: R80.1 U18.F8(MGTRREF_216)

Not connected (* = marked no-connect by the designer): U18 A6(MGTPTXN2_216)* AA9(NC)* AA10(NC)* AA11(NC)* AA13(NC)* AA14(NC)* AA15(NC)* AA16(NC)* AB10(NC)* AB11(NC)* AB12(NC)* AB13(NC)* AB15(NC)* AB16(NC)* AB17(NC)* B6(MGTPTXP2_216)* C5(MGTPTXN1_216)* C7(MGTPTXN3_216)* D5(MGTPTXP1_216)* D7(MGTPTXP3_216)* E10(MGTREFCLK1N_216)* F10(MGTREFCLK1P_216)* T14(NC)* T15(NC)* T16(NC)* U15(NC)* U16(NC)* V10(NC)* V13(NC)* V14(NC)* V15(NC)* W10(NC)* W11(NC)* W12(NC)* W14(NC)* W15(NC)* W16(NC)* Y11(NC)* Y12(NC)* Y13(NC)* Y14(NC)* Y16(NC)* Y17(NC)*

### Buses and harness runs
bus SW[10..1] = port SW[10..1]
bus XADCMUX[3..0] = port XADCMUX[3..0]

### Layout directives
differential pair: CLOCK.ACLK_N, CLOCK.ACLK_P, CLOCK.ACNV_N, CLOCK.ACNV_P, CLOCK.AIN_N, CLOCK.AIN_P, CLOCK.CNTROUT_N, CLOCK.CNTROUT_P, CLOCK.OSCCLK_N, CLOCK.OSCCLK_P, CLOCK.SYNC_N, CLOCK.SYNC_P, DAC_REF.DOUT0_N, DAC_REF.DOUT0_P, DAC_REF.DOUT1_N, DAC_REF.DOUT1_P, DAC_REF.DSCLK_N, DAC_REF.DSCLK_P, DAC_REF.DSYNC_N, DAC_REF.DSYNC_P, DAC_REF.INVSYNC_N, DAC_REF.INVSYNC_P, DAC_REF.REFCLK_N, DAC_REF.REFCLK_P, PCIE.PCIE_CLK_N, PCIE.PCIE_CLK_P, PCIE.PCIE_RX0_N, PCIE.PCIE_RX0_P, PCIE.PCIE_TX0_N, PCIE.PCIE_TX0_P, POWER.PWRSYNC_N, POWER.PWRSYNC_P, S1_16.S1_N, S1_16.S1_P, S1_16.S2_N, S1_16.S2_P, S1_16.S3_N, S1_16.S3_P, S1_16.S4_N, S1_16.S4_P, S1_16.S5_N, S1_16.S5_P, S1_16.S6_N, S1_16.S6_P, S1_16.S7_N, S1_16.S7_P, S1_16.S8_N, S1_16.S8_P, S1_16.S9_N, S1_16.S9_P, S10_N, S10_P, S11_N, S11_P, S12_N, S12_P, S13_N, S13_P, S14_N, S14_P, S15_N, S15_P, S16_N, S16_P, S17_32.S17_N, S17_32.S17_P, S17_32.S18_N, S17_32.S18_P, S17_32.S19_N, S17_32.S19_P, S17_32.S20_N, S17_32.S20_P, S17_32.S21_N, S17_32.S21_P, S17_32.S22_N, S17_32.S22_P, S17_32.S23_N, S17_32.S23_P, S17_32.S24_N, S17_32.S24_P, S17_32.S25_N, S17_32.S25_P, S17_32.S26_N, S17_32.S26_P, S17_32.S27_N, S17_32.S27_P, S17_32.S28_N, S17_32.S28_P, S17_32.S29_N, S17_32.S29_P, S17_32.S30_N, S17_32.S30_P, S17_32.S31_N, S17_32.S31_P, S17_32.S32_N, S17_32.S32_P, S33_48.S33_N, S33_48.S33_P, S33_48.S34_N, S33_48.S34_P, S33_48.S35_N, S33_48.S35_P, S33_48.S36_N, S33_48.S36_P, S33_48.S37_N, S33_48.S37_P, S33_48.S38_N, S33_48.S38_P, S33_48.S39_N, S33_48.S39_P, S33_48.S40_N, S33_48.S40_P, S33_48.S41_N, S33_48.S41_P, S33_48.S42_N, S33_48.S42_P, S33_48.S43_N, S33_48.S43_P, S33_48.S44_N, S33_48.S44_P, S33_48.S45_N, S33_48.S45_P, S33_48.S46_N, S33_48.S46_P, S33_48.S47_N, S33_48.S47_P, S33_48.S48_N, S33_48.S48_P, S49_64.S49_N, S49_64.S49_P, S49_64.S50_N, S49_64.S50_P, S49_64.S51_N, S49_64.S51_P, S49_64.S52_N, S49_64.S52_P, S49_64.S53_N, S49_64.S53_P, S49_64.S54_N, S49_64.S54_P, S49_64.S55_N, S49_64.S55_P, S49_64.S56_N, S49_64.S56_P, S49_64.S57_N, S49_64.S57_P, S49_64.S58_N, S49_64.S58_P, S49_64.S59_N, S49_64.S59_P, S49_64.S60_N, S49_64.S60_P, S49_64.S61_N, S49_64.S61_P, S49_64.S62_N, S49_64.S62_P, S49_64.S63_N, S49_64.S63_P, S49_64.S64_N, S49_64.S64_P, SFPIN.SYNCIN_N, SFPIN.SYNCIN_P, SFPIN.SYNCOUT_N, SFPIN.SYNCOUT_P, T1_11.T1_N, T1_11.T1_P, T1_11.T2_N, T1_11.T2_P, T1_11.T3_N, T1_11.T3_P, T1_11.T4_N, T1_11.T4_P, T1_11.T5_N, T1_11.T5_P, T1_11.T6_N, T1_11.T6_P, T1_11.T7_N, T1_11.T7_P, T1_11.T8_N, T1_11.T8_P, T1_11.T9_N, T1_11.T9_P, T10_N, T10_P, T11_N, T11_P

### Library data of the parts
R80 = ChipRes1: Resistor, surface mount; Tolerance: 1%
U18 = CMP-0383-00019-1: Artix-7 FPGA, 250 User I/Os, 4 GTP, 484-Ball BGA, Speed Grade 2, Commercial Grade, Pb-Free; Manufacturer: Xilinx; Total Block RAM: 1800 Kb; GTP: 4; Available User I/O: 250; Speed Grades: 2; Logic Cells: 33280; CMTs: 5

## Sheet PCI Express_16765X11115_36PIN_Half length.schdoc: PCIe Interface
size B; Organization: Organization; Address1: Address1; Address2: Address2; Address3: Address3; Address4: Address4; DocumentNumber: 11; Revision: 0; SheetNumber: 11; SheetTotal: 12
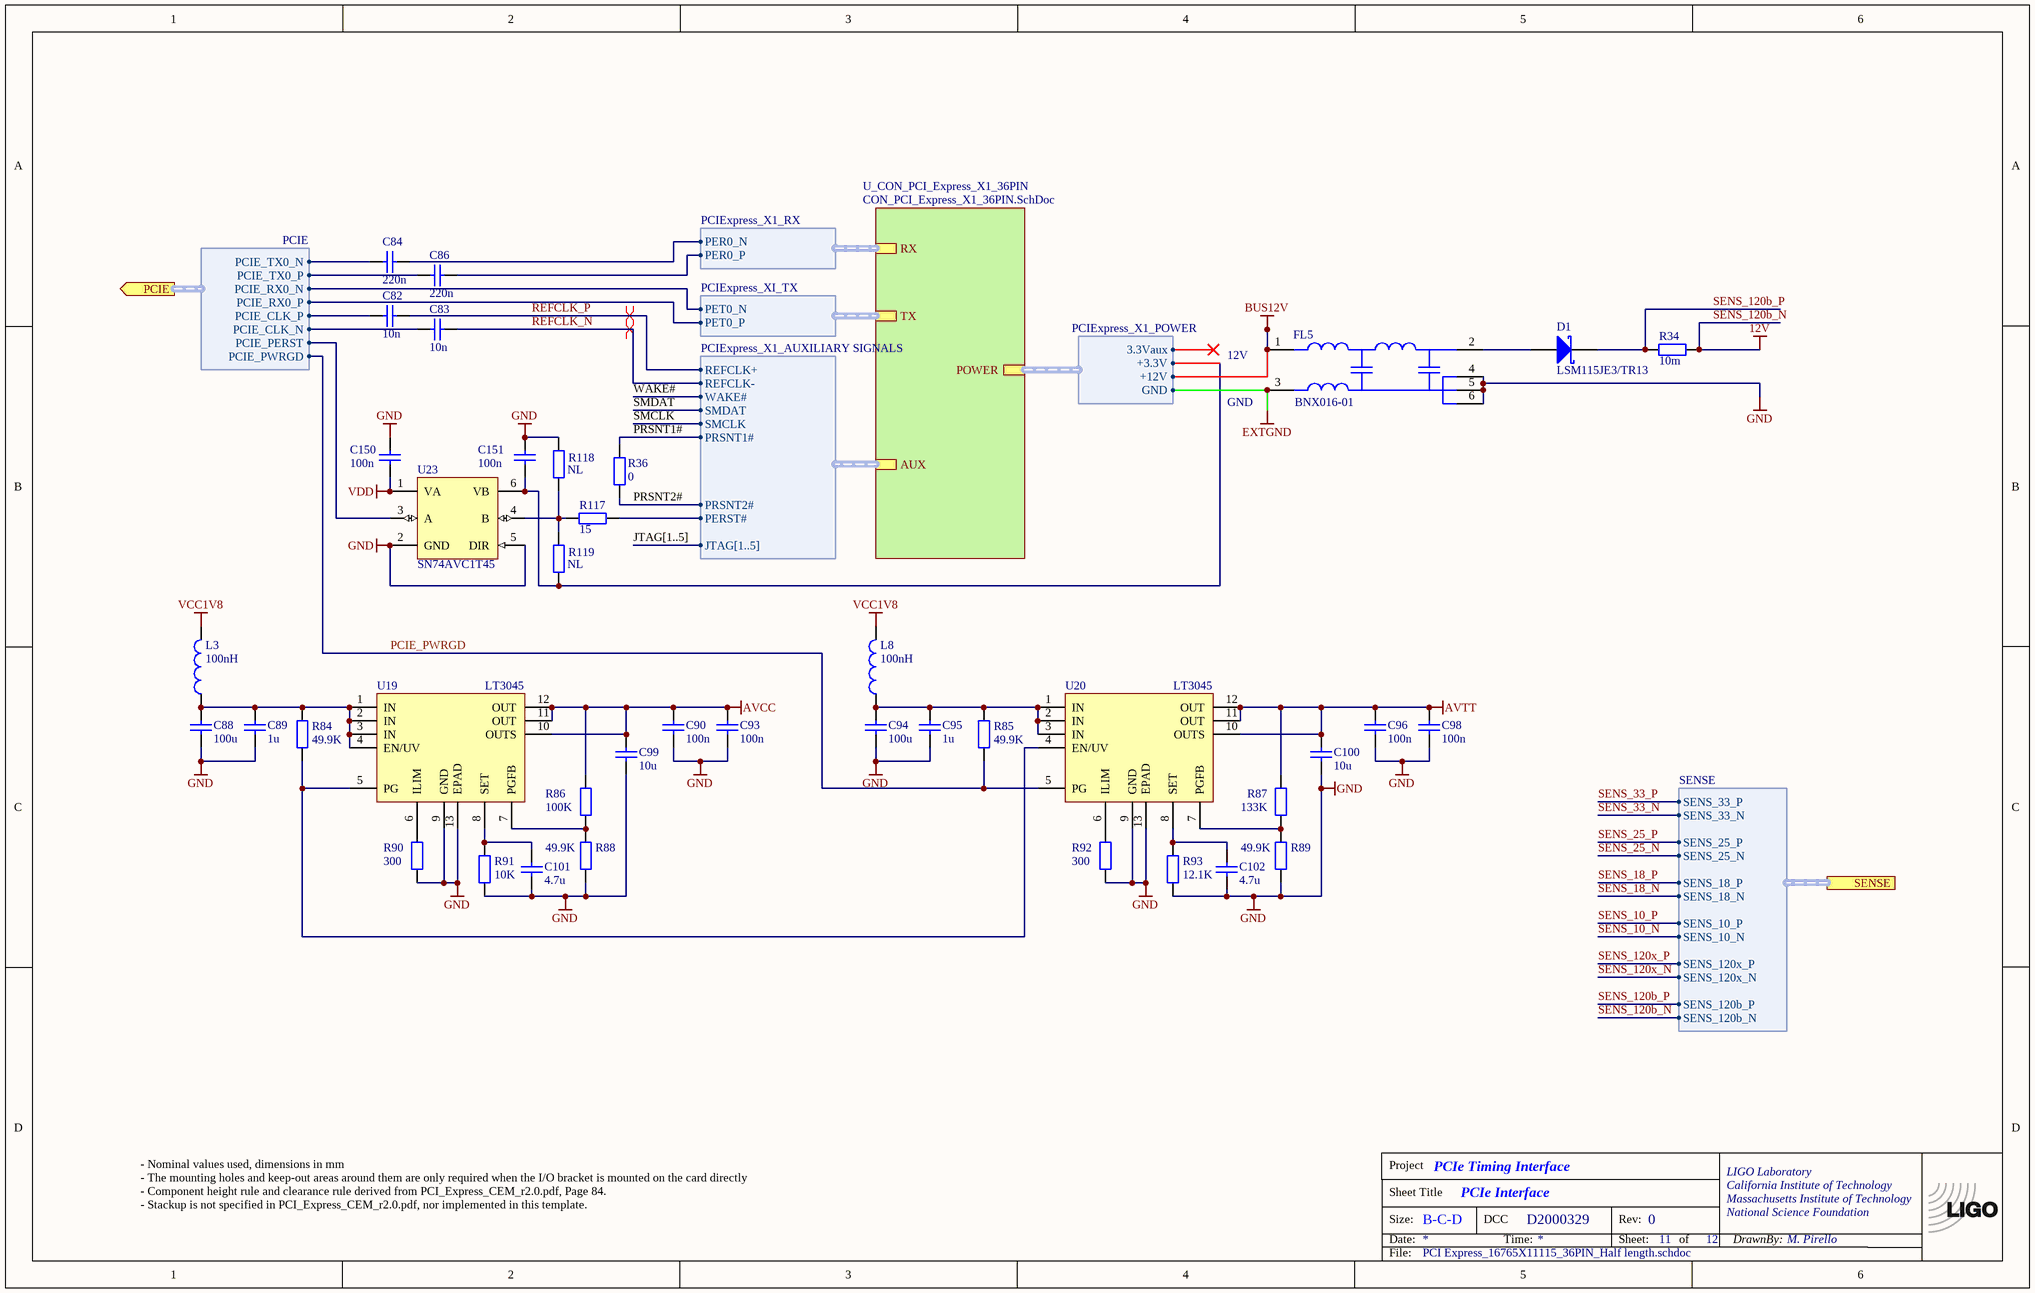
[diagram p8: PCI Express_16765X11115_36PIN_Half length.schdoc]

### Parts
(Parts that share a designator on the sheet are numbered #1, #2 ... from top to bottom, then left to right.)
*?#5  TitleBlock  (value not drawn)  (graphical)
C82  10n  [CC1005-0402]
C83  10n  [CC1005-0402]
C84  220n  [CC1005-0402]
C86  220n  [CC1005-0402]
C88  100u  [CC3225-1210]
C89  1u  [CC2013-0805]
C90  100n  [CC1005-0402]
C93  100n  [CC1005-0402]
C94  100u  [CC3225-1210]
C95  1u  [CC2013-0805]
C96  100n  [CC1005-0402]
C98  100n  [CC1005-0402]
C99  10u  [CC2013-0805]
C100  10u  [CC2013-0805]
C101  4.7u  [CC2013-0805]
C102  4.7u  [CC2013-0805]
C150  100n  [CC1005-0402]
C151  100n  [CC1005-0402]
D1  LSM115JE3/TR13  [MCSM-DO-214BA-2_L]
FL5  BNX016-01  [MURA-BNX016-01_V]
L3  100nH  [CL2520-1008]
L8  100nH  [CL2520-1008]
R34  10m  [CR3225-1210]
R36  0  [CR1005-0402]
R84  49.9K  [CR1005-0402]
R85  49.9K  [CR1005-0402]
R86  100K  [CR1005-0402]
R87  133K  [CR1005-0402]
R88  49.9K  [CR1005-0402]
R89  49.9K  [CR1005-0402]
R90  300  [CR1005-0402]
R91  10K  [CR1005-0402]
R92  300  [CR1005-0402]
R93  12.1K  [CR1005-0402]
R117#1  15  [CR1005-0402]
R118#1  NL  [CR1005-0402]
R119#1  NL  [CR1005-0402]
U19  LT3045  [MSOP12_PAD]
U20  LT3045  [MSOP12_PAD]
U23  SN74AVC1T45  [SC70]

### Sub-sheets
U_CON_PCI_Express_X1_36PIN = CON_PCI_Express_X1_36PIN.SchDoc (file not in this document): POWER (harness PCIExpress_X1_POWER), AUX (harness PCIExpress_X1_AUXILIARY SIGNALS), RX (harness PCIExpress_X1_RX), TX (harness PCIExpress_XI_TX)

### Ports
PCIE (out, harness PCIE), SENSE (harness SENSE)

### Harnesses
PCIExpress_X1_RX: PER0_N, PER0_P
PCIExpress_XI_TX: PET0_N, PET0_P
PCIExpress_X1_POWER: +3.3V, +12V, GND, 3.3Vaux
PCIExpress_X1_AUXILIARY SIGNALS: JTAG[1..5], PERST#, PRSNT1#, PRSNT2#, REFCLK+, REFCLK-, SMCLK, SMDAT, WAKE#
PCIE: PCIE_CLK_N, PCIE_CLK_P, PCIE_RX0_N, PCIE_RX0_P, PCIE_TX0_N, PCIE_TX0_P, PCIE_PERST, PCIE_PWRGD
SENSE: SENS_33_P, SENS_33_N, SENS_25_P, SENS_25_N, SENS_18_P, SENS_18_N, SENS_10_P, SENS_10_N, SENS_120x_P, SENS_120x_N, SENS_120b_P, SENS_120b_N

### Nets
12V: R34.2 ; port SENSE.SENS_120x_N, port SENSE.SENS_120b_N  [also labelled SENS_120b_N, SENS_120x_N]
AVCC: C90.2 C93.2 C99.2 R86.2 U19.10(OUTS) U19.11(OUT) U19.12(OUT)
AVTT: C96.2 C98.2 C100.2 R87.2 U20.10(OUTS) U20.11(OUT) U20.12(OUT)
BUS12V: FL5.1(B) ; sheet U_CON_PCI_Express_X1_36PIN/POWER.+12V
GND: C88.1 C89.1 C90.1 C93.1 C94.1 C95.1 C96.1 C98.1 C99.1 C100.1 C101.1 C102.1 C150.2 C151.2 FL5.3(PSG) FL5.4(CG) FL5.5(CG) FL5.6(CG) R88.1 R89.1 R90.1 R91.1 R92.1 R93.1 R118#1.1 U19.9(GND) U19.13(EPAD) U20.9(GND) U20.13(EPAD) U23.2(GND) U23.5(DIR) ; sheet U_CON_PCI_Express_X1_36PIN/POWER.GND  [also labelled EXTGND]
VCC1V8: L3.2 L8.2 ; port SENSE.SENS_18_N  [also labelled SENS_18_N]
VDD: C150.1 U23.1(VA) ; port SENSE.SENS_25_N  [also labelled SENS_25_N]
PCIE.PCIE_CLK_N: C83.2 ; port PCIE.PCIE_CLK_N
PCIE.PCIE_CLK_P: C82.2 ; port PCIE.PCIE_CLK_P
PCIE.PCIE_PERST: U23.3(A) ; port PCIE.PCIE_PERST
PCIE.PCIE_RX0_N: sheet U_CON_PCI_Express_X1_36PIN/TX.PET0_N, port PCIE.PCIE_RX0_N
PCIE.PCIE_RX0_P: sheet U_CON_PCI_Express_X1_36PIN/TX.PET0_P, port PCIE.PCIE_RX0_P
PCIE.PCIE_TX0_N: C84.2 ; port PCIE.PCIE_TX0_N
PCIE.PCIE_TX0_P: C86.2 ; port PCIE.PCIE_TX0_P
PCIE_PWRGD: R85.1 U20.5(PG) ; port PCIE.PCIE_PWRGD  [project net PCIE.PCIE_PWRGD]
PRSNT1#: R36.2 ; sheet U_CON_PCI_Express_X1_36PIN/AUX.PRSNT1#
PRSNT2#: R36.1 ; sheet U_CON_PCI_Express_X1_36PIN/AUX.PRSNT2#
REFCLK_N: C83.1 ; sheet U_CON_PCI_Express_X1_36PIN/AUX.REFCLK-
REFCLK_P: C82.1 ; sheet U_CON_PCI_Express_X1_36PIN/AUX.REFCLK+
SENS_120b_P: D1.2(K) R34.1 ; port SENSE.SENS_120b_P  [project net SENSE.SENS_120b_P]
NetC84_1: C84.1 ; sheet U_CON_PCI_Express_X1_36PIN/RX.PER0_N
NetC86_1: C86.1 ; sheet U_CON_PCI_Express_X1_36PIN/RX.PER0_P
NetC88_2: C88.2 C89.2 L3.1 R84.2 U19.1(IN) U19.2(IN) U19.3(IN) U19.4(EN/UV)
NetC94_2: C94.2 C95.2 L8.1 R85.2 U20.1(IN) U20.2(IN) U20.3(IN)
NetC101_2: C101.2 R91.2 U19.8(SET)
NetC102_2: C102.2 R93.2 U20.8(SET)
NetC151_1: C151.1 R119#1.2 U23.6(VB) ; sheet U_CON_PCI_Express_X1_36PIN/POWER.+3.3V
NetD1_1: D1.1(A) FL5.2(CB)
NetR84_1: R84.1 U19.5(PG) U20.4(EN/UV)
NetR86_1: R86.1 R88.2 U19.7(PGFB)
NetR87_1: R87.1 R89.2 U20.7(PGFB)
NetR90_2: R90.2 U19.6(ILIM)
NetR92_2: R92.2 U20.6(ILIM)
NetR117#1_1: R117#1.1 ; sheet U_CON_PCI_Express_X1_36PIN/AUX.PERST#
NetR117#1_2: R117#1.2 R118#1.2 R119#1.1 U23.4(B)

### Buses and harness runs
bus JTAG[1..5]

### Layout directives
differential pair: REFCLK_N, REFCLK_P

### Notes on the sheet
- (near FL5) 12V
- (near FL5) GND
- - Nominal values used, dimensions in mm
  - The mounting holes and keep-out areas around them are only required when the I/O bracket is mounted on the card directly
  - Component height rule and clearance rule derived from PCI_Express_CEM_r2.0.pdf, Page 84.
  - Stackup is not specified in PCI_Express_CEM_r2.0.pdf, nor implemented in this template.

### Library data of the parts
C82-C84 C86 C88-C90 C93-C96 C98-C102 C150 C151 = ChipCap: Capacitor, surface mount; Tolerance: 10%
D1 = CMP-2000-06604-1: Ultra Low Forward Voltage Schottky Rectifier, 15 V, -55 to 100 degC, 2-Pin Molded, RoHS, Tape and Reel; Manufacturer: MicrosemiCorporation; Voltage - Forward (Vf) (Max) @ If: 220mV@1A; Current - Average Rectified (Io): 1A; Voltage - DC Reverse (Vr) (Max): 15V; Current - Reverse Leakage @ Vr: 10mA@15V; Speed: FastRecovery=200mA(Io)
FL5 = CMP-2000-05960-1: Block Type EMIFIL(R) Reference Specification, 15 A, 25 V, -40 to 125 degC, 6-Pin THD, RoHS, Bulk; Manufacturer: Murata; Maximum Current Rating: 15A; Operating Frequency: 100kHz→1GHz; Maximum Voltage Rating: 25Vdc
L3 L8 = ChipInductor: Inductor; Part Number: 1008LS-101XJLB
R34 = ChipRes1: Resistor, surface mount; Tolerance: 1%
R36 R84-R93 R117#1 R118#1 R119#1 = ChipRes1: Resistor, surface mount; Tolerance: 0.1%
U19 U20 = LT3045: 20V, 500mA, Ultralow Noise, / Ultrahigh PSRR Linear Regulator; Part Number: LT3045EMSE#PBF-ND
U23 = SN74LVC1T45: Single-Bit Dual Supply Transceiver

## Sheet ChassisTimingInterface6.SchDoc: Duotone
size B; Author: M. Pirello; Organization: LIGO Laboratory; Address1: California Institute of Technology; Address2: Massachusetts Institute of Technology; Address3: National Science Foundation; Address4: Australia 2086; DocumentNumber: 8; SheetNumber: 8; SheetTotal: 12; Size: B
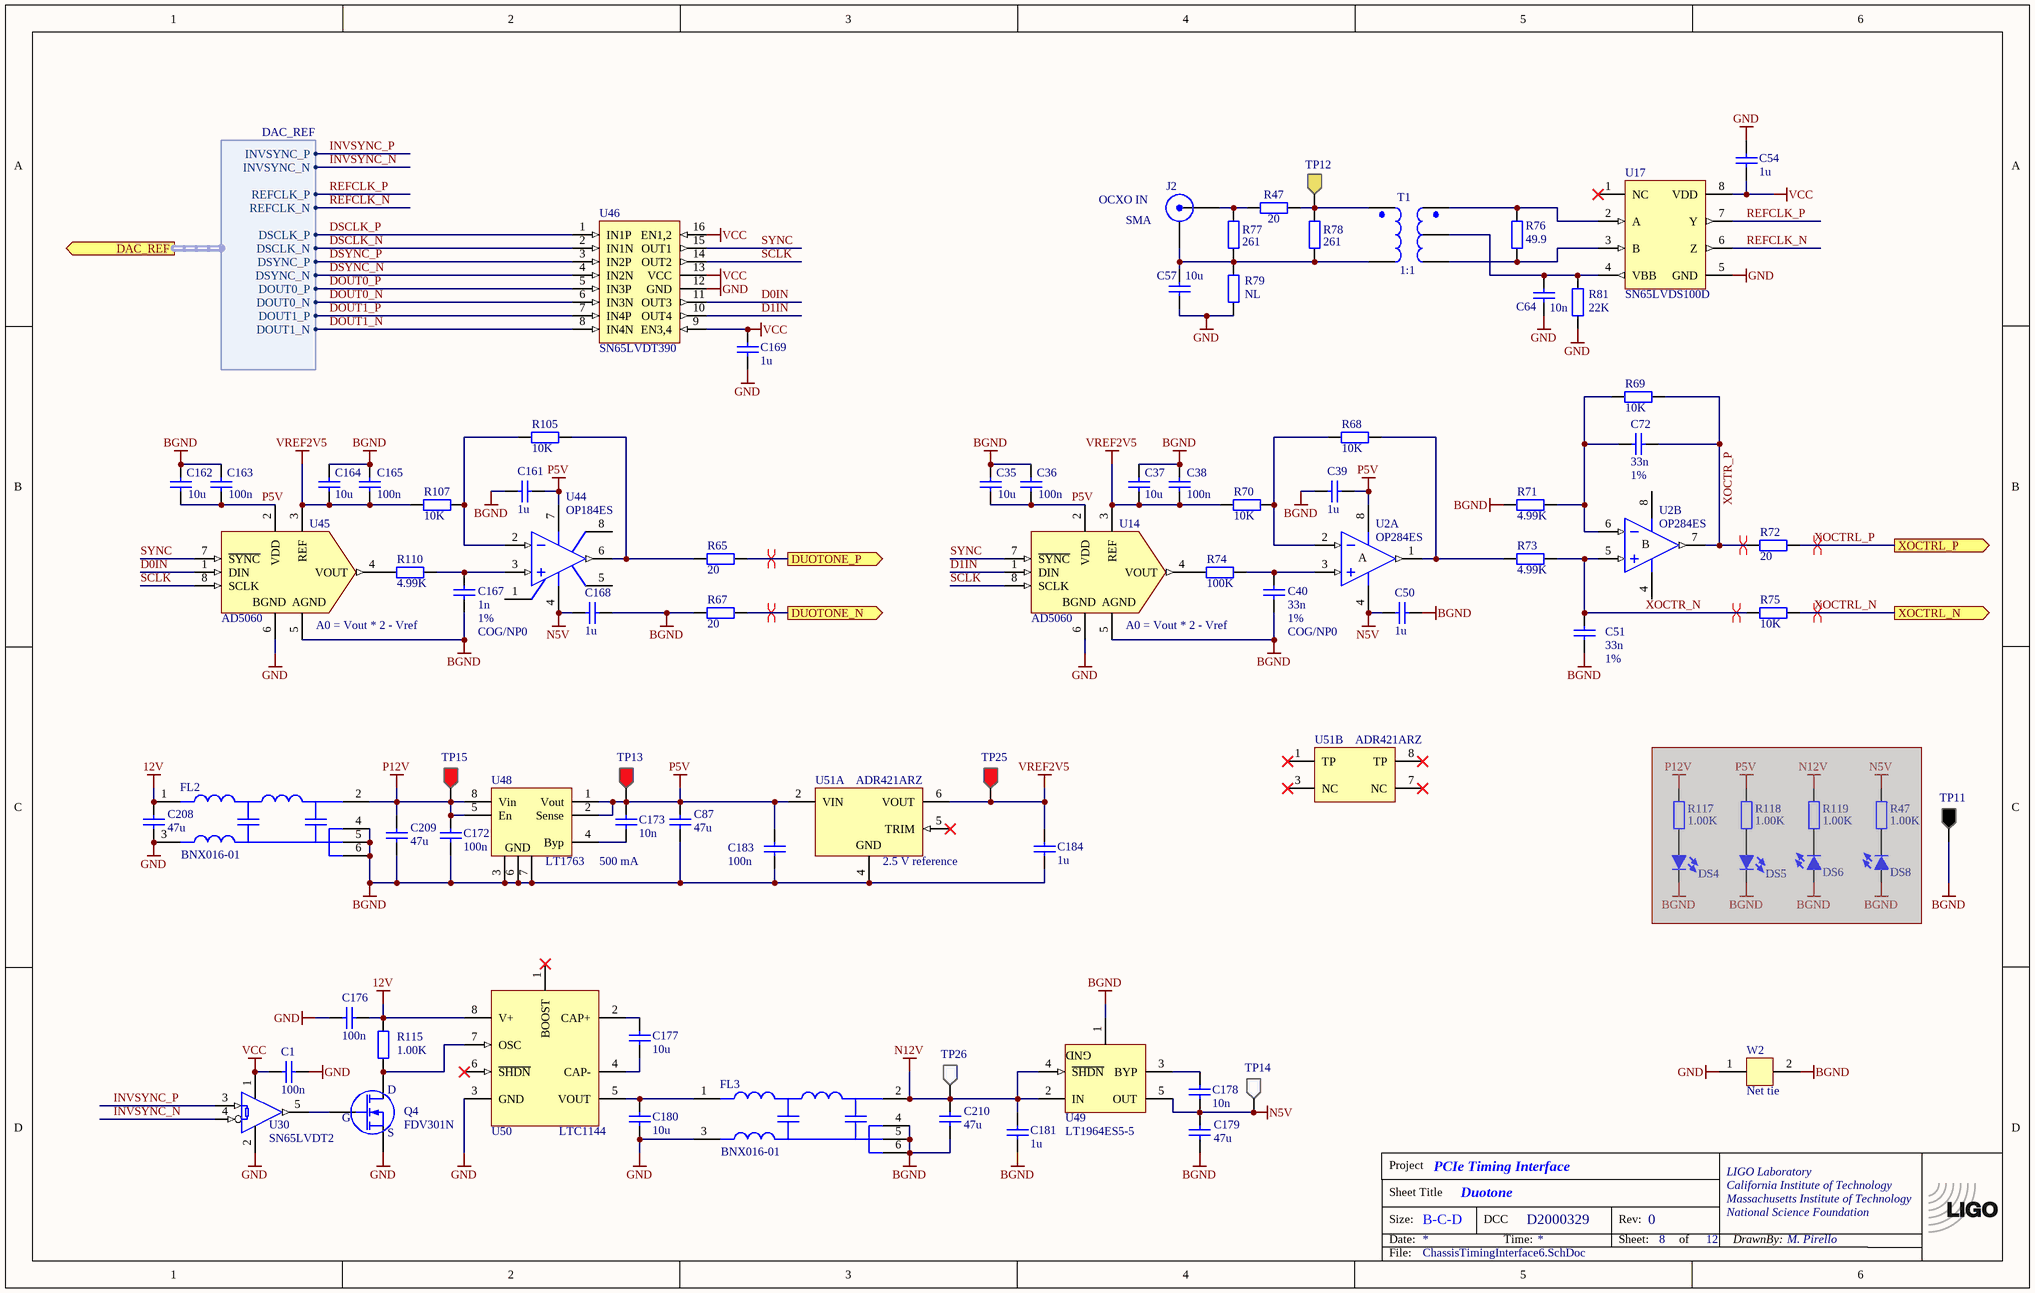
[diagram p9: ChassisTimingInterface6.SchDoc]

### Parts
(Parts that share a designator on the sheet are numbered #1, #2 ... from top to bottom, then left to right.)
*?#6  TitleBlock  (value not drawn)  (graphical)
?#1  (no value)  (no BOM)
C1  100n  [CC2013-0805]
C35  10u  [CC2013-0805]
C36  100n  [CC2013-0805]
C37  10u  [CC2013-0805]
C38  100n  [CC2013-0805]
C39  1u  [CC2013-0805]
C40  Tolerance: 1%  Material: COG/NP0  [CC2013-0805]  (hidden comment: 33n)
C50  1u  [CC2013-0805]
C51  Tolerance: 1%  [CC2013-0805]  (hidden comment: 33n)
C54  1u  [CC2013-0805]
C57  10u  [CC2013-0805]
C64  10n  [CC2013-0805]
C72  Tolerance: 1%  [CC3216-1206]  (hidden comment: 33n)
C87  47u  [CC3216-1206]
C161  1u  [CC2013-0805]
C162  10u  [CC2013-0805]
C163  100n  [CC2013-0805]
C164  10u  [CC2013-0805]
C165  100n  [CC2013-0805]
C167  Tolerance: 1%  Material: COG/NP0  [CC2013-0805]  (hidden comment: 1n)
C168  1u  [CC2013-0805]
C169  1u  [CC2013-0805]
C172  100n  [CC2013-0805]
C173  10n  [CC2013-0805]
C176  100n  [CC2013-0805]
C177  10u  [CC3216-1206]
C178  10n  [CC2013-0805]
C179  47u  [CC3216-1206]
C180  10u  [CC3216-1206]
C181  1u  [CC2013-0805]
C183  100n  [CC2013-0805]
C184  1u  [CC2013-0805]
C208  47u  [CC3216-1206]
C209  47u  [CC3216-1206]
C210  47u  [CC3216-1206]
DS4  LED  [LED-0805]  (value not drawn)  (masked out: inside a compile mask, not in the netlist)
DS5  LED  [LED-0805]  (value not drawn)  (masked out: inside a compile mask, not in the netlist)
DS6  LED  [LED-0805]  (value not drawn)  (masked out: inside a compile mask, not in the netlist)
DS8  LED  [LED-0805]  (value not drawn)  (masked out: inside a compile mask, not in the netlist)
FL2  BNX016-01  [MURA-BNX016-01_V]
FL3  BNX016-01  [MURA-BNX016-01_V]
J2  SMA  [SMA-RA]
Q4  FDV301N  [SO-G3/C2.25]
R47#1  20  [CR3216-1206]
R47#2  1.00K  [CR2012-0805]  (masked out: inside a compile mask, not in the netlist)
R65  20  [CR2012-0805]
R67  20  [CR2012-0805]
R68  10K  [CR2012-0805]
R69  10K  [CR2012-0805]
R70  10K  [CR2012-0805]
R71  4.99K  [CR2012-0805]
R72  20  [CR1005-0402]
R73  4.99K  [CR2012-0805]
R74  100K  [CR2012-0805]
R75  10K  [CR1005-0402]
R76  49.9  [CR3216-1206]
R77  261  [CR2012-0805]
R78  261  [CR3216-1206]
R79  NL  [CR2012-0805]
R81  22K  [CR2012-0805]
R105  10K  [CR2012-0805]
R107  10K  [CR2012-0805]
R110  4.99K  [CR2012-0805]
R115  1.00K  [CR1005-0402]
R117#2  1.00K  [CR2012-0805]  (masked out: inside a compile mask, not in the netlist)
R118#2  1.00K  [CR2012-0805]  (masked out: inside a compile mask, not in the netlist)
R119#2  1.00K  [CR2012-0805]  (masked out: inside a compile mask, not in the netlist)
T1  1:1  [AT224-3]
TP11  Testpoint  [TP1-BLK]  (value not drawn)
TP12  Testpoint  [TP1-YLW]  (value not drawn)
TP13  Testpoint  [TP1-RED]  (value not drawn)
TP14  Testpoint  [TP1-WHT]  (value not drawn)
TP15  Testpoint  [TP1-RED]  (value not drawn)
TP25  Testpoint  [TP1-RED]  (value not drawn)
TP26  Testpoint  [TP1-WHT]  (value not drawn)
U2  OP284ES  [SO-8_N]  (parts A,B of 2)
U14  AD5060  [SSO-G8/SM8]
U17  SN65LVDS100D  [MSOP8]
U30  SN65LVDT2  [SO-G5/E2.4]
U44  OP184ES  [SO-8_N]
U45  AD5060  [SSO-G8/SM8]
U46  SN65LVDT390  [TSSOP16]
U48  LT1763  [SO-G8]
U49  LT1964ES5-5  [LT-S5-5-TSOT-23_M]
U50  LTC1144  [SO-G8]
U51  ADR421ARZ  [ADI-R-8_M]  (parts A,B of 2)
W2  Net tie  [NETTIE1_BOTH]  (net tie, no BOM)

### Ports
DAC_REF (out, harness DAC_REF), DUOTONE_N (out), DUOTONE_P (out), XOCTRL_N (out), XOCTRL_P (out)

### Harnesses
DAC_REF: DSCLK_N, DSCLK_P, DSYNC_N, DSYNC_P, DOUT0_N, DOUT0_P, DOUT1_N, DOUT1_P, REFCLK_N, REFCLK_P, INVSYNC_N, INVSYNC_P

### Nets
12V: C176.1 C208.2 FL2.1(B) R115.2 U50.8(V+)
BGND: C35.2 C36.2 C37.2 C38.2 C39.1 C40.1 C50.2 C51.1 C87.1 C161.1 C162.2 C163.2 C164.2 C165.2 C167.2 C168.2 C172.1 C179.1 C181.1 C183.1 C184.1 C209.1 C210.1 FL2.4(CG) FL2.5(CG) FL2.6(CG) FL3.4(CG) FL3.5(CG) FL3.6(CG) R67.1 R71.1 TP11.1 U14.5(AGND) U45.5(AGND) U48.3(GND) U48.6(GND) U48.7(GND) U49.1(GND) U51.4(GND) W2.2
GND: C1.1 C54.2 C57.1 C64.1 C169.1 C176.2 C180.1 C208.1 FL2.3(PSG) FL3.3(PSG) Q4.2(S) R79.2 R81.2 U14.6(BGND) U17.5(GND) U30.2(GND) U45.6(BGND) U46.12(GND) U50.3(GND) W2.1
N5V: C50.1 C168.1 C178.1 C179.2 TP14.1 U2.4(V-) U44.4(V-) U49.5(OUT)
N12V: C181.2 C210.2 FL3.2(CB) TP26.1 U49.2(IN) U49.4(~{SHDN})
P5V: C35.1 C36.1 C39.2 C87.2 C161.2 C162.1 C163.1 C173.2 C183.2 TP13.1 U2.8(V+) U14.2(VDD) U44.7(V+) U45.2(VDD) U48.1(Vout) U48.2(Sense) U51.2(VIN)
P12V: C172.2 C209.2 FL2.2(CB) TP15.1 U48.5(En) U48.8(Vin)
VCC: C1.2 C54.1 C169.2 U17.8(VDD) U30.1(VCC) U46.9(EN3,4) U46.13(VCC) U46.16(EN1,2)
VREF2V5: C37.1 C38.1 C164.1 C165.1 C184.2 R70.1 R107.1 TP25.1 U14.3(REF) U45.3(REF) U51.6(VOUT)
D0IN: U45.1(DIN) U46.11(OUT3)
D1IN: U14.1(DIN) U46.10(OUT4)
DOUT0_N: U46.6(IN3N) ; port DAC_REF.DOUT0_N  [project net DAC_REF.DOUT0_N]
DOUT0_P: U46.5(IN3P) ; port DAC_REF.DOUT0_P  [project net DAC_REF.DOUT0_P]
DOUT1_N: U46.8(IN4N) ; port DAC_REF.DOUT1_N  [project net DAC_REF.DOUT1_N]
DOUT1_P: U46.7(IN4P) ; port DAC_REF.DOUT1_P  [project net DAC_REF.DOUT1_P]
DSCLK_N: U46.2(IN1N) ; port DAC_REF.DSCLK_N  [project net DAC_REF.DSCLK_N]
DSCLK_P: U46.1(IN1P) ; port DAC_REF.DSCLK_P  [project net DAC_REF.DSCLK_P]
DSYNC_N: U46.4(IN2N) ; port DAC_REF.DSYNC_N  [project net DAC_REF.DSYNC_N]
DSYNC_P: U46.3(IN2P) ; port DAC_REF.DSYNC_P  [project net DAC_REF.DSYNC_P]
DUOTONE_N: R67.2 ; port DUOTONE_N
DUOTONE_P: R65.2 ; port DUOTONE_P
INVSYNC_N: U30.4(B) ; port DAC_REF.INVSYNC_N  [project net DAC_REF.INVSYNC_N]
INVSYNC_P: U30.3(A) ; port DAC_REF.INVSYNC_P  [project net DAC_REF.INVSYNC_P]
REFCLK_N: U17.6(Z) ; port DAC_REF.REFCLK_N  [project net DAC_REF.REFCLK_N]
REFCLK_P: U17.7(Y) ; port DAC_REF.REFCLK_P  [project net DAC_REF.REFCLK_P]
SCLK: U14.8(SCLK) U45.8(SCLK) U46.14(OUT2)
SYNC: U14.7(~{SYNC}) U45.7(~{SYNC}) U46.15(OUT1)
XOCTR_N: C51.2 R73.2 R75.1 U2.5(IN+)
XOCTR_P: C72.1 R69.2 R72.1 U2.7(OUT)
XOCTRL_N: R75.2 ; port XOCTRL_N
XOCTRL_P: R72.2 ; port XOCTRL_P
NetC40_2: C40.2 R74.2 U2.3(IN+)
NetC57_2: C57.2 J2.2(Y) R77.1 R78.1 R79.1 T1.4
NetC64_2: C64.2 R81.1 T1.2 U17.4(VBB)
NetC72_2: C72.2 R69.1 R71.2 U2.6(IN-)
NetC167_1: C167.1 R110.2 U44.3(IN+)
NetC173_1: C173.1 U48.4(Byp)
NetC177_1: C177.1 U50.4(CAP-)
NetC177_2: C177.2 U50.2(CAP+)
NetC178_2: C178.2 U49.3(BYP)
NetC180_2: C180.2 FL3.1(B) U50.5(VOUT)
NetJ2_1: J2.1(X) R47#1.2 R77.2
NetQ4_1: Q4.1(G) U30.5(R)
NetQ4_3: Q4.3(D) R115.1 U50.7(OSC)
NetR47#1_1: R47#1.1 R78.2 T1.6 TP12.1
NetR65_1: R65.1 R105.2 U44.6(OUT)
NetR68_1: R68.1 R70.2 U2.2(IN-)
NetR68_2: R68.2 R73.1 U2.1(OUT)
NetR74_1: R74.1 U14.4(VOUT)
NetR76_1: R76.1 T1.3 U17.3(B)
NetR76_2: R76.2 T1.1 U17.2(A)
NetR105_1: R105.1 R107.2 U44.2(IN-)
NetR110_1: R110.1 U45.4(VOUT)

Not connected (* = marked no-connect by the designer): U17 1(NC)*; U44 1(NUL) 5(NUL) 8(NC); U50 1(BOOST)* 6(~{SHDN})*; U51 1(TP)* 3(NC)* 5(TRIM)* 7(NC)* 8(TP)*

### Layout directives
differential pair: DUOTONE_N, DUOTONE_P, XOCTR_N, XOCTR_P, XOCTRL_N, XOCTRL_P

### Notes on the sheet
- (near J2) OCXO IN
- (near U45) A0 = Vout * 2 - Vref
- (near U14) A0 = Vout * 2 - Vref
- 500 mA
- (near U51) 2.5 V reference

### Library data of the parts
?#1 = LIGO_logo: LIGO logo
C1 C35-C39 C50 C54 C87 C161-C165 C168 C169 C172 C173 C176-C181 C183 C184 C208-C210 = ChipCap: Capacitor, surface mount; Tolerance: 10%
C40 = ChipCap: Capacitor, surface mount; Part Number: 490-1763-1-ND; Voltage Rating: 25V
C51 C72 = ChipCap: Capacitor, surface mount; Part Number: 490-1763-1-ND; Voltage Rating: 25V; Material: COG/NP0
C57 = ChipCap: Capacitor, surface mount; Part Number: 1276-6472-1-ND; Tolerance: 10%
C64 = ChipCap: Capacitor, surface mount; Part Number: 490-1642-1-ND; Tolerance: 10%
C167 = ChipCap: Capacitor, surface mount
DS4-DS6 DS8 = LED: Panel mount LED
FL2 FL3 = CMP-2000-05960-1: as FL5 on sheet PCI Express_16765X11115_36PIN_Half length
J2 = SMA: SMA, PCB Mount, Right Angle
Q4 = FDV301N: FDV301N, Digital FET, N-channel, SOT23; Part Number: FDV301NCT-ND
R47#1 = ChipRes1: Resistor, surface mount; Part Number: 311-0.0ERCT-ND; Tolerance: 1%
R47#2 R65 R67 R72 R77-R79 R81 R115 R117#2 R118#2 R119#2 = ChipRes1: Resistor, surface mount; Tolerance: 1%
R68-R71 R73 R75 R105 R107 R110 = ChipRes1: Resistor, surface mount; Tolerance: 0.1%
R74 = ChipRes1: Resistor, surface mount; Part Number: RG20P100KBCT-ND; Tolerance: 0.1%
R76 = ChipRes1: Resistor, surface mount; Part Number: 311-200FRCT-ND; Tolerance: 1%
T1 = TC1.5-52: Transformer 1:4, wide band, 0.5-300 MHz; Part Number: TC1-1TX+
TP11 = TP_GND: Testpoint, black; Part Number: 5006K-ND
TP12 = TP_SIGNAL: Testpoint, yellow; Part Number: 5009K-ND
TP13 TP15 TP25 = TP_POSITIVE: Testpoint, red; Part Number: 5005K-ND
TP14 TP26 = TP_NEGATIVE: Testpoint, white; Part Number: 5007K-ND
U2 = OP284ES: Precision Rail-to-Rail Input and Output Operational Amplifier
U14 U45 = AD5060: 16 bit DAC, 250kSPS, unipolar, serial
U17 = SN65LVDS100: DIFF TRANSLATOR; Part Number: 296-13624-5-ND
U30 = SN65LVDT2DBV: Single LVDS Receiver with 100 Ohm termination
U44 = OP184ES: Precision Rail-to-Rail Input and Ouput Operational Amplifier; Note: Pin 8 is not connected.
U46 = SN65LVDT390: Quad LVDS Receiver with 100 Ohm termination
U48 = LT1763: Positive voltage regulator
U49 = CMP-0476-01338-1: 200 mA, Low Noise, Low Dropout Negative Micropower Regulator, -1.9 to -20 V Vin, -5 V Vout, 5-pin SOT23 (S5-5), -40 to 125 degC, Pb-Free, Mini Tape and Reel; PartNumber: LT1964ES5-5#TRMPBF; Manufacturer: Linear Technology; PSRR(dB): 54; Discrete Pass Element: no; Dropout Voltage(V): 0.34; Shutdown Current(uA): 3; Isupply(mA): 0.03; Iout(mA): 200; Number of Outputs: 1; Output Voltage: -5 V; Noise(uV): 30
U50 = LTC1144: Switched capacitor voltage inverter
U51 = CMP-0784-00214-1: Ultraprecision, Low Noise, XFET(R) Voltage Reference, 2.5 V Output, 4.5 to 18 V Supply, Industrial, 8-pin SOIC (R-8), Tube; Manufacturer: Analog Devices; Ref Out TC (ppm/C): 2; Max V Supply (V): 18; Vout: 2.5V; Min V Supply (V): 4.5
W2 = NetTie1: Tie two nets together

## Sheet ChassisTimingInterface_SFP.SchDoc: SFP
size B; Author: M. Pirello; Organization: LIGO Laboratory; Address1: California Institute of Technology; Address2: Massachusetts Institute of Technology; Address3: National Science Foundation; Address4: Australia 2086; DocumentNumber: 3; SheetNumber: 3; SheetTotal: 12; Size: B
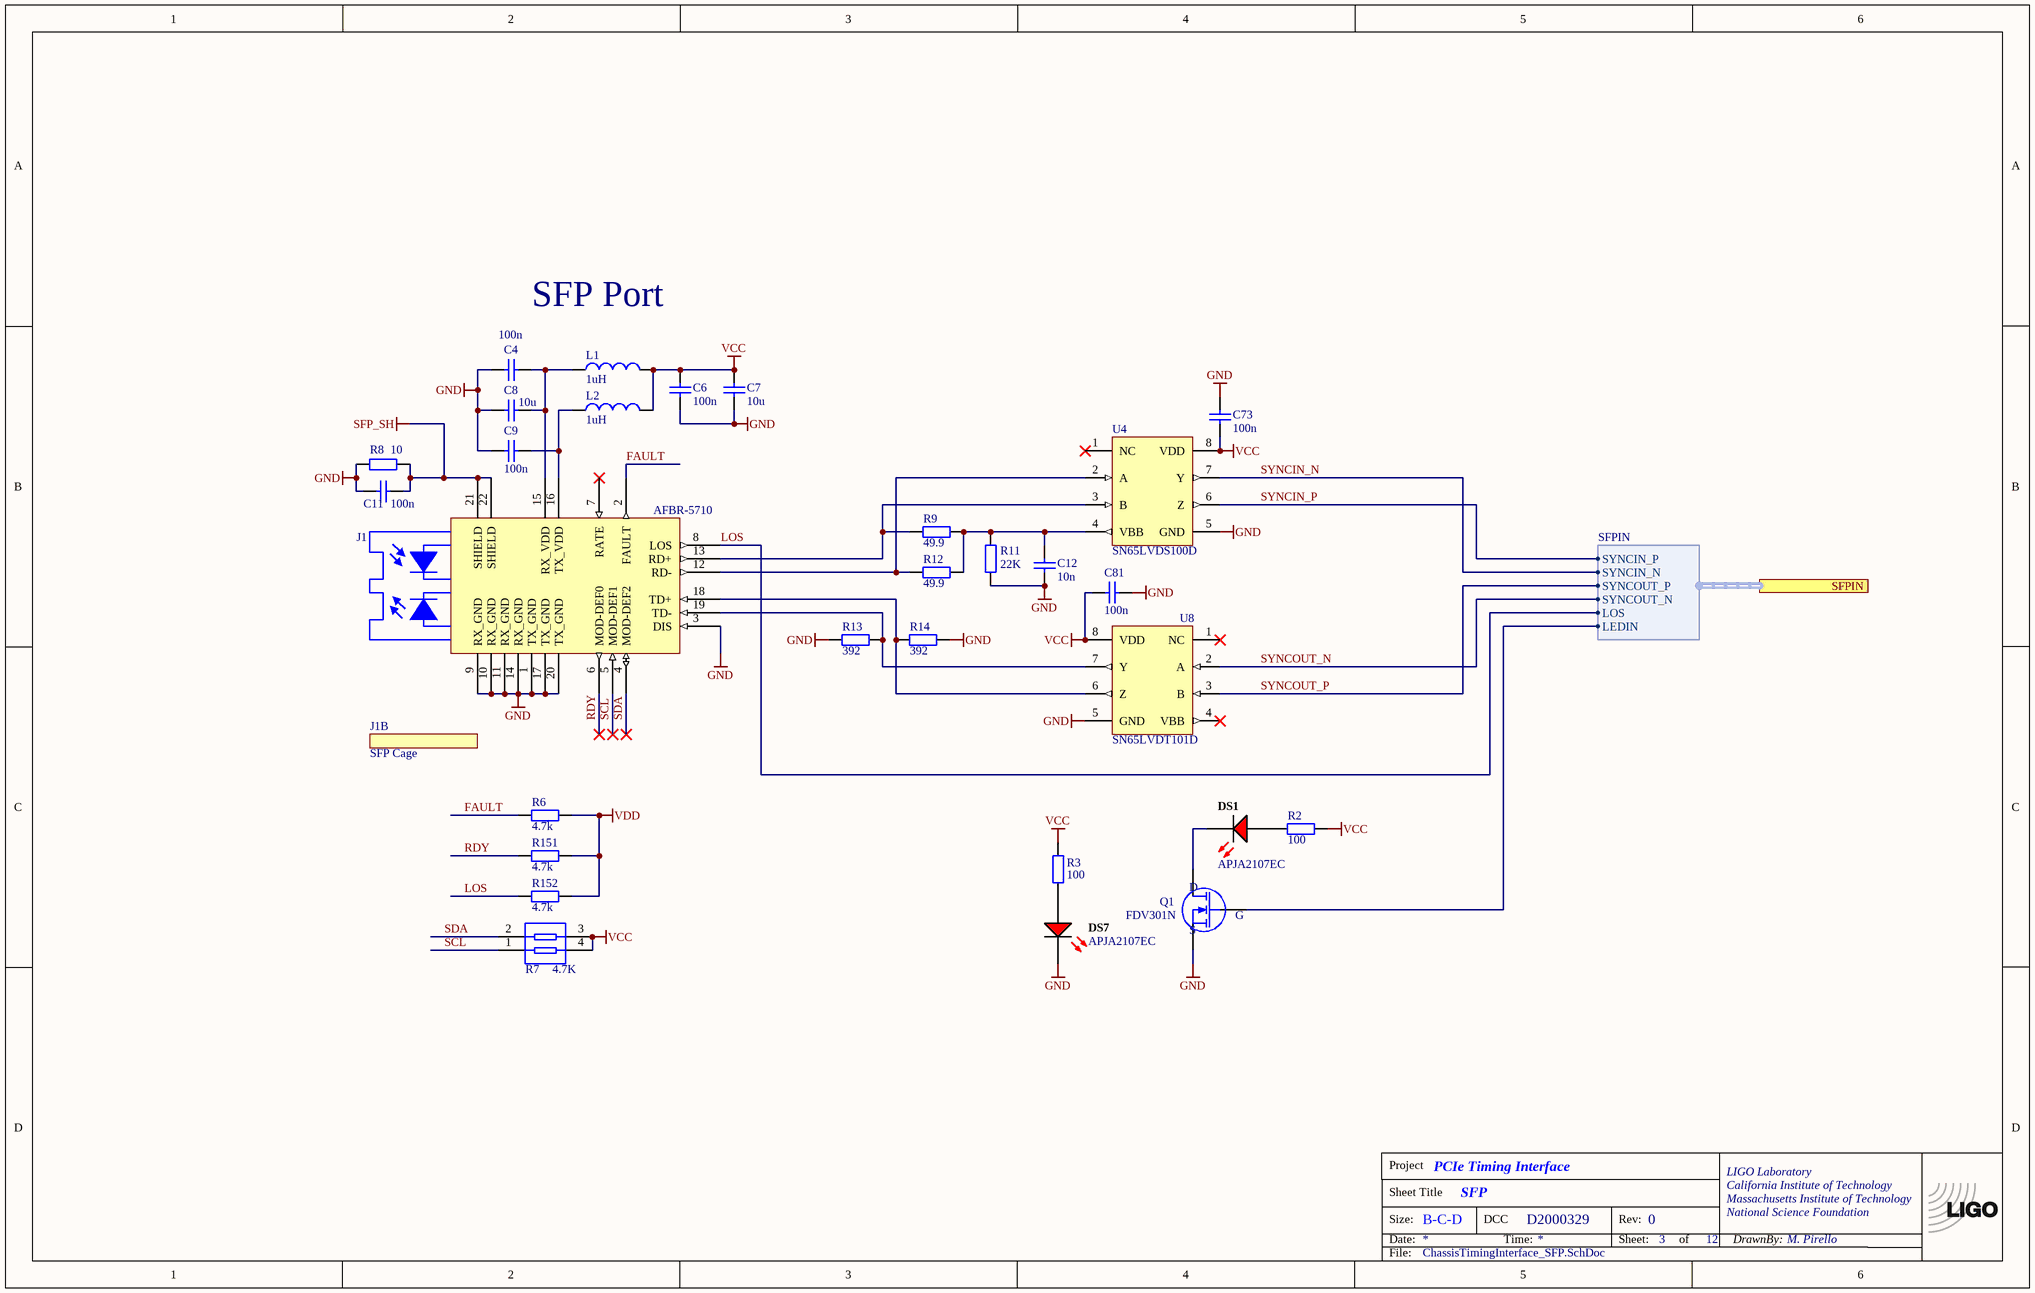
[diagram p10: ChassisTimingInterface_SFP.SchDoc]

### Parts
(Parts that share a designator on the sheet are numbered #1, #2 ... from top to bottom, then left to right.)
*#3  TitleBlock  (value not drawn)  (graphical)
C4  100n  [CC2013-0805]
C6  100n  [CC2013-0805]
C7  10u  [CC2013-0805]
C8  10u  [CC2013-0805]
C9  100n  [CC2013-0805]
C11  100n  [CC2013-0805]
C12  10n  [CC2013-0805]
C73  100n  [CC2013-0805]
C81  100n  [CC2013-0805]
DS1  APJA2107EC  [KING-LED2107-13-RED-2_V]
DS7  APJA2107EC  [KING-LED2107-13-RED-2_V]
J1  AFBR-5710  [MSA/SFP2x10]
J1B  SFP Cage  (mechanical)
L1  1uH  [CL2520-1008]
L2  1uH  [CL2520-1008]
Q1  FDV301N  [SO-G3/C2.25]
R2  100  [CR2012-0805]
R3  100  [CR2012-0805]
R6  4.7k  [CR1005-0402]
R7  value 4.7K  [RES4-0.8]  (hidden comment: Resistor Array)
R8  10  [CR2012-0805]
R9  49.9  [CR2012-0805]
R11  22K  [CR2012-0805]
R12  49.9  [CR2012-0805]
R13  392  [CR2012-0805]
R14  392  [CR2012-0805]
R151  4.7k  [CR1005-0402]
R152  4.7k  [CR1005-0402]
U4  SN65LVDS100D  [MSOP8]
U8  SN65LVDT101D  [MSOP8]

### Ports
SFPIN (harness SFPIN)

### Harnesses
SFPIN: SYNCIN_N, SYNCIN_P, SYNCOUT_N, SYNCOUT_P, LEDIN, LOS

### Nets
GND: C4.1 C6.1 C7.1 C8.1 C9.1 C11.2 C12.1 C73.1 C81.1 DS7.1(K) J1.1(TX_GND) J1.3(DIS) J1.9(RX_GND) J1.10(RX_GND) J1.11(RX_GND) J1.14(RX_GND) J1.17(TX_GND) J1.20(TX_GND) Q1.2(S) R8.2 R11.2 R13.1 R14.2 U4.5(GND) U8.5(GND)
SFP_SH: C11.1 J1.21(SHIELD) J1.22(SHIELD) R8.1
VCC: C6.2 C7.2 C73.2 C81.2 L1.2 L2.2 R2.2 R3.2 R7.3 R7.4 U4.8(VDD) U8.8(VDD)
VDD: R6.2 R151.2 R152.2
FAULT: J1.2(FAULT) R6.1
LOS: J1.8(LOS) R152.1 ; port SFPIN.LOS  [project net SFPIN.LOS]
RDY: J1.6(MOD-DEF0) R151.1
SCL: J1.5(MOD-DEF1) R7.1
SDA: J1.4(MOD-DEF2) R7.2
SFPIN.LEDIN: Q1.1(G) ; port SFPIN.LEDIN
SYNCIN_N: U4.7(Y) ; port SFPIN.SYNCIN_N  [project net SFPIN.SYNCIN_N]
SYNCIN_P: U4.6(Z) ; port SFPIN.SYNCIN_P  [project net SFPIN.SYNCIN_P]
SYNCOUT_N: U8.2(A) ; port SFPIN.SYNCOUT_N  [project net SFPIN.SYNCOUT_N]
SYNCOUT_P: U8.3(B) ; port SFPIN.SYNCOUT_P  [project net SFPIN.SYNCOUT_P]
NetC4_2: C4.2 C8.2 J1.15(RX_VDD) L1.1
NetC9_2: C9.2 J1.16(TX_VDD) L2.1
NetC12_2: C12.2 R9.1 R11.1 R12.1 U4.4(VBB)
NetDS1_1: DS1.1(K) Q1.3(D)
NetDS1_2: DS1.2(A) R2.1
NetDS7_2: DS7.2(A) R3.1
NetJ1_12: J1.12(RD-) R12.2 U4.2(A)
NetJ1_13: J1.13(RD+) R9.2 U4.3(B)
NetJ1_18: J1.18(TD+) R14.1 U8.6(Z)
NetJ1_19: J1.19(TD-) R13.2 U8.7(Y)

Not connected (* = marked no-connect by the designer): J1 7(RATE)* 23(POST) 24(POST); U4 1(NC)*; U8 1(NC)* 4(VBB)*

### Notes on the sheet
- SFP Port

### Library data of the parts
C4 C6-C9 C11 C12 C73 C81 = ChipCap: Capacitor, surface mount; Tolerance: 10%
DS1 DS7 = CMP-0245-00001-1: 2.1x0.7mm Right Angle SMT LED, 1.3mm Thickness, Red; Forward Current: 30 mA; Reverse Voltage: 5 V; Power Dissipation: 75 mW
J1 = AFBR-5710: fiber optic transceiver, 1.25GB/s, MM, LC, SFP
J1B = Partlist: Part Number: WM1634-ND
L1 L2 = ChipInductor: Inductor
Q1 = FDV301N: as Q4 on sheet ChassisTimingInterface6
R2 R3 R6 R8 R9 R11-R14 R151 R152 = ChipRes1: Resistor, surface mount; Tolerance: 1%
R7 = RES2_ARRAY: Resistor Network, parallel, 2 resistors; CTS_742C043: 0.8mm spacing, 1.6mm wide; CTS_743C043: 1.27mm spacing, 2mm wide; CTS_744C043: 1.27mm spacing, 3.2mm wide; CTS_741X043: 0.5mm spacing, 1mm wide
U4 = SN65LVDS100: as U17 on sheet ChassisTimingInterface6
U8 = SN65LVDS100: DIFF TRANSLATOR; Part Number: 296-15391-5-ND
